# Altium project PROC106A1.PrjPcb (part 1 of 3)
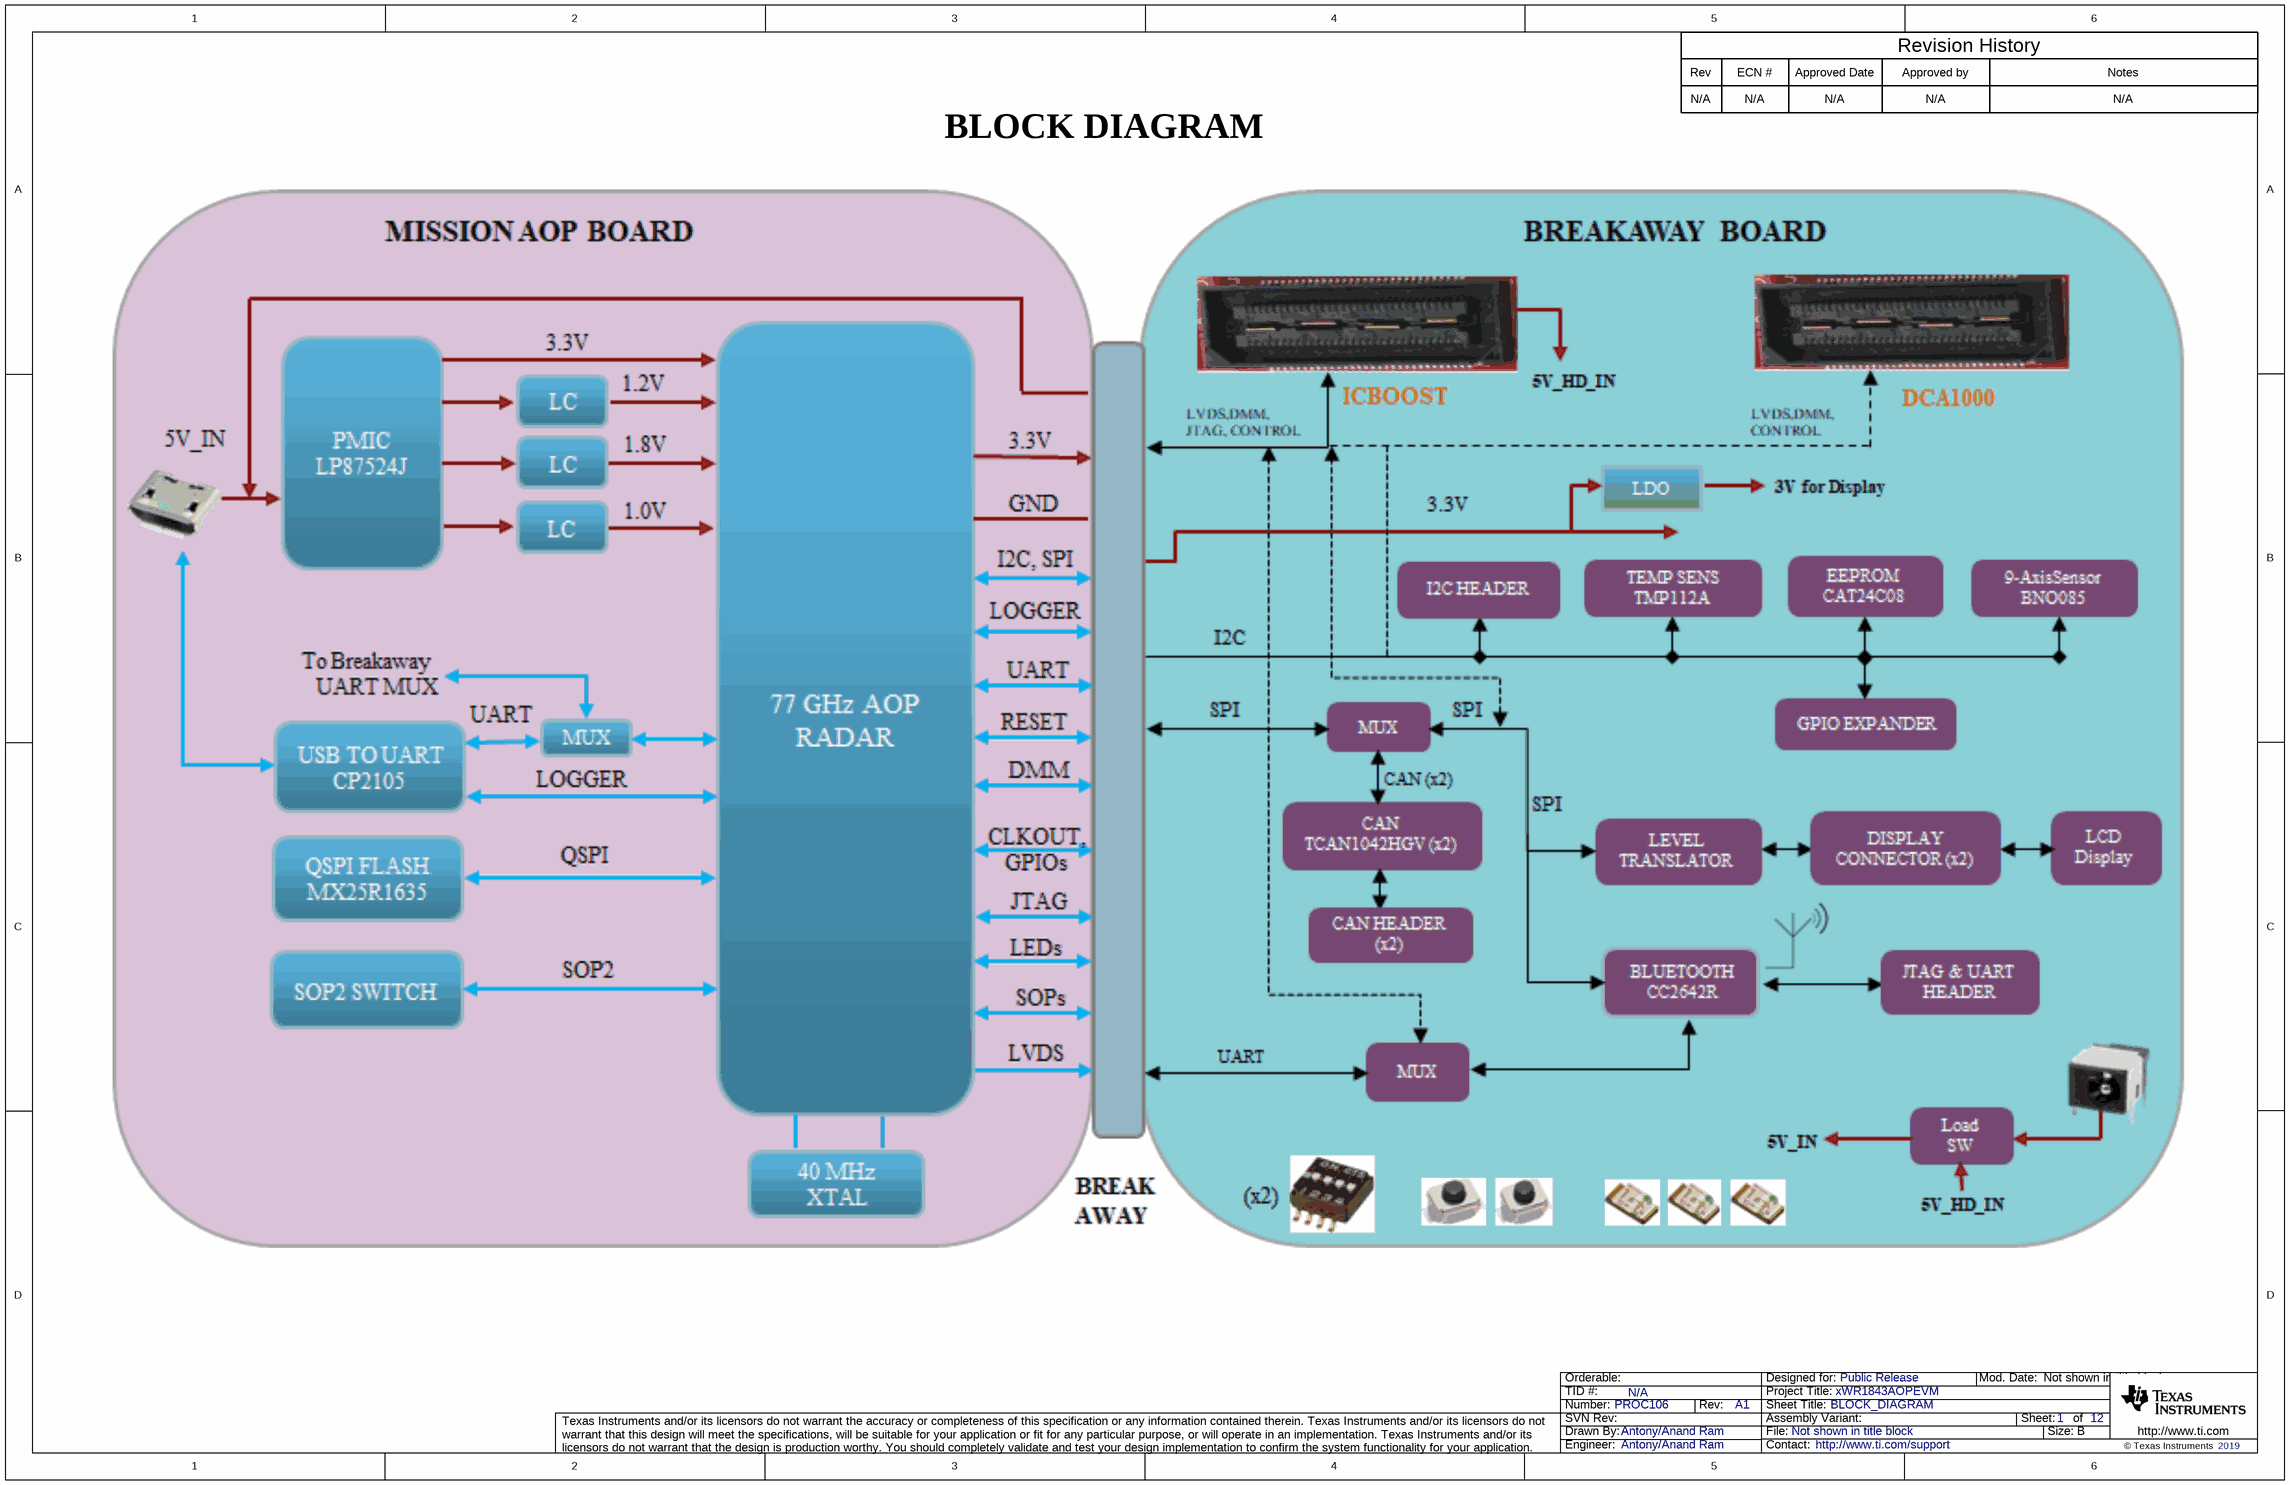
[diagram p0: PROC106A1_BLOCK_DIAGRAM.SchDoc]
CopyrightYear: 2019; PCB_Layout: Mistral Team; PCB_Rev: A1; PRJ_Customer: Public Release; PRJ_Engineer: Antony/Anand Ram; PRJ_Number: PROC106; PRJ_Title: xWR1843AOPEVM; SCH_Rev: A1; TechSupport: http://www.ti.com/support; TID: N/A
12 sheets, 430 parts. Net scope: flat (ports and power ports of the same name join across sheets).
Board file: PROC106A1.PcbDoc
Sheets:
  PROC106A1_BLOCK_DIAGRAM.SchDoc
  PROC106A1_TABLEOFCONTENTS.SchDoc
  PROC106A1_AOP_IO.SchDoc
  PROC106A1_AOP_PWR.SchDoc
  PROC106A1_PMIC.SchDoc
  PROC106A1_FLASH_USB_TO_UART.SchDoc
  PROC106A1_HD_CONN_PWR_SW.SchDoc
  PROC106A1_RST_GPIOs_I2C.SchDoc
  PROC106A1_BT_DISPLAY.SchDoc
  PROC106A1_ANALOG_MUX.SchDoc
  PROC106A1_CAN_INTERFACE.SchDoc
  PROC106A1_Hardware.schdoc

## Sheet PROC106A1_BLOCK_DIAGRAM.SchDoc: BLOCK_DIAGRAM
size 431 x 279 mm; Date: Not shown in title block; ApprovedBy: Not shown in title block; CheckedBy: Not shown in title block; Author: Not shown in title block; CompanyName: Not shown in title block; DrawnBy: Antony/Anand Ram; Engineer: Not shown in title block; Organization: Not shown in title block; Address1: Not shown in title block; Address2: Not shown in title block; Address3: Not shown in title block; Address4: Not shown in title block; DocumentNumber: 1; Revision: Use project parameter SCH_Rev; SheetNumber: 1; SheetTotal: 12; PageSetup: Record=PageOptions¦CenterHorizontal=True¦CenterVertical=True¦PrintScale=1.00¦XCorrection=1.00¦YCorrection=1.00¦PrintKind=0¦BorderSize=5000000¦LeftOffset=0¦BottomOffset=0¦Orientation=2¦PaperLength=1000¦PaperWidth=1000¦Scale=100¦PaperSource=15¦PrintQuality=600¦MediaType=1¦DitherType=10¦PaperKind=Letter¦PrintScaleMode=1

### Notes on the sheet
- Rev
- N/A
- ECN #
- Approved Date
- Approved by
- Revision History
- Notes
- BLOCK DIAGRAM

## Sheet PROC106A1_TABLEOFCONTENTS.SchDoc: TABLE_OF_CONTENTS
size 431 x 279 mm; Date: Not shown in title block; ApprovedBy: Not shown in title block; CheckedBy: Not shown in title block; Author: Not shown in title block; CompanyName: Not shown in title block; DrawnBy: Antony/Anand Ram; Engineer: Not shown in title block; Organization: Not shown in title block; Address1: Not shown in title block; Address2: Not shown in title block; Address3: Not shown in title block; Address4: Not shown in title block; DocumentNumber: 2; Revision: Use project parameter SCH_Rev; SheetNumber: 2; SheetTotal: 12; PageSetup: Record=PageOptions¦CenterHorizontal=True¦CenterVertical=True¦PrintScale=1.00¦XCorrection=1.00¦YCorrection=1.00¦PrintKind=0¦BorderSize=5000000¦LeftOffset=0¦BottomOffset=0¦Orientation=2¦PaperLength=1000¦PaperWidth=1000¦Scale=100¦PaperSource=15¦PrintQuality=600¦MediaType=1¦DitherType=10¦PaperKind=Letter¦PrintScaleMode=1
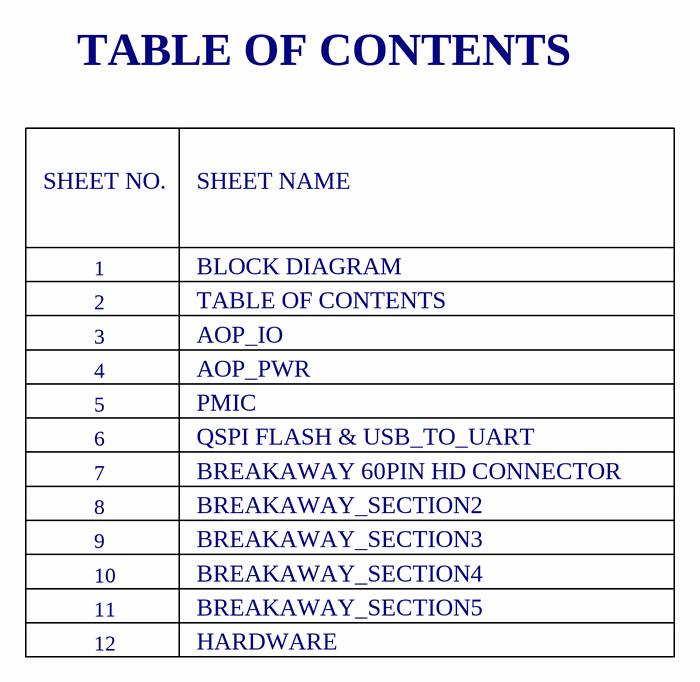
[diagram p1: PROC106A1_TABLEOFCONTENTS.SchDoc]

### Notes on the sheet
- TABLE OF CONTENTS
- SHEET NO.
- SHEET NAME
- 1
- 2
- 3
- BLOCK DIAGRAM
- AOP_IO
- 4
- 5
- AOP_PWR
- PMIC
- 7
- 8
- 6
- QSPI FLASH & USB_TO_UART
- BREAKAWAY 60PIN HD CONNECTOR
- BREAKAWAY_SECTION2
- 9
- 10
- BREAKAWAY_SECTION3
- BREAKAWAY_SECTION4
- 11
- 12
- HARDWARE
- BREAKAWAY_SECTION5

## Sheet PROC106A1_AOP_IO.SchDoc: AOP_IO
size 431 x 279 mm; Date: Not shown in title block; ApprovedBy: Not shown in title block; CheckedBy: Not shown in title block; Author: Not shown in title block; CompanyName: Not shown in title block; DrawnBy: Antony/Anand Ram; Engineer: Not shown in title block; Organization: Not shown in title block; Address1: Not shown in title block; Address2: Not shown in title block; Address3: Not shown in title block; Address4: Not shown in title block; DocumentNumber: 3; Revision: Use project parameter SCH_Rev; SheetNumber: 3; SheetTotal: 12; PageSetup: Record=PageOptions¦CenterHorizontal=True¦CenterVertical=True¦PrintScale=1.00¦XCorrection=1.00¦YCorrection=1.00¦PrintKind=0¦BorderSize=5000000¦LeftOffset=0¦BottomOffset=0¦Orientation=2¦PaperLength=1000¦PaperWidth=1000¦Scale=100¦PaperSource=15¦PrintQuality=600¦MediaType=1¦DitherType=10¦PaperKind=Letter¦PrintScaleMode=1
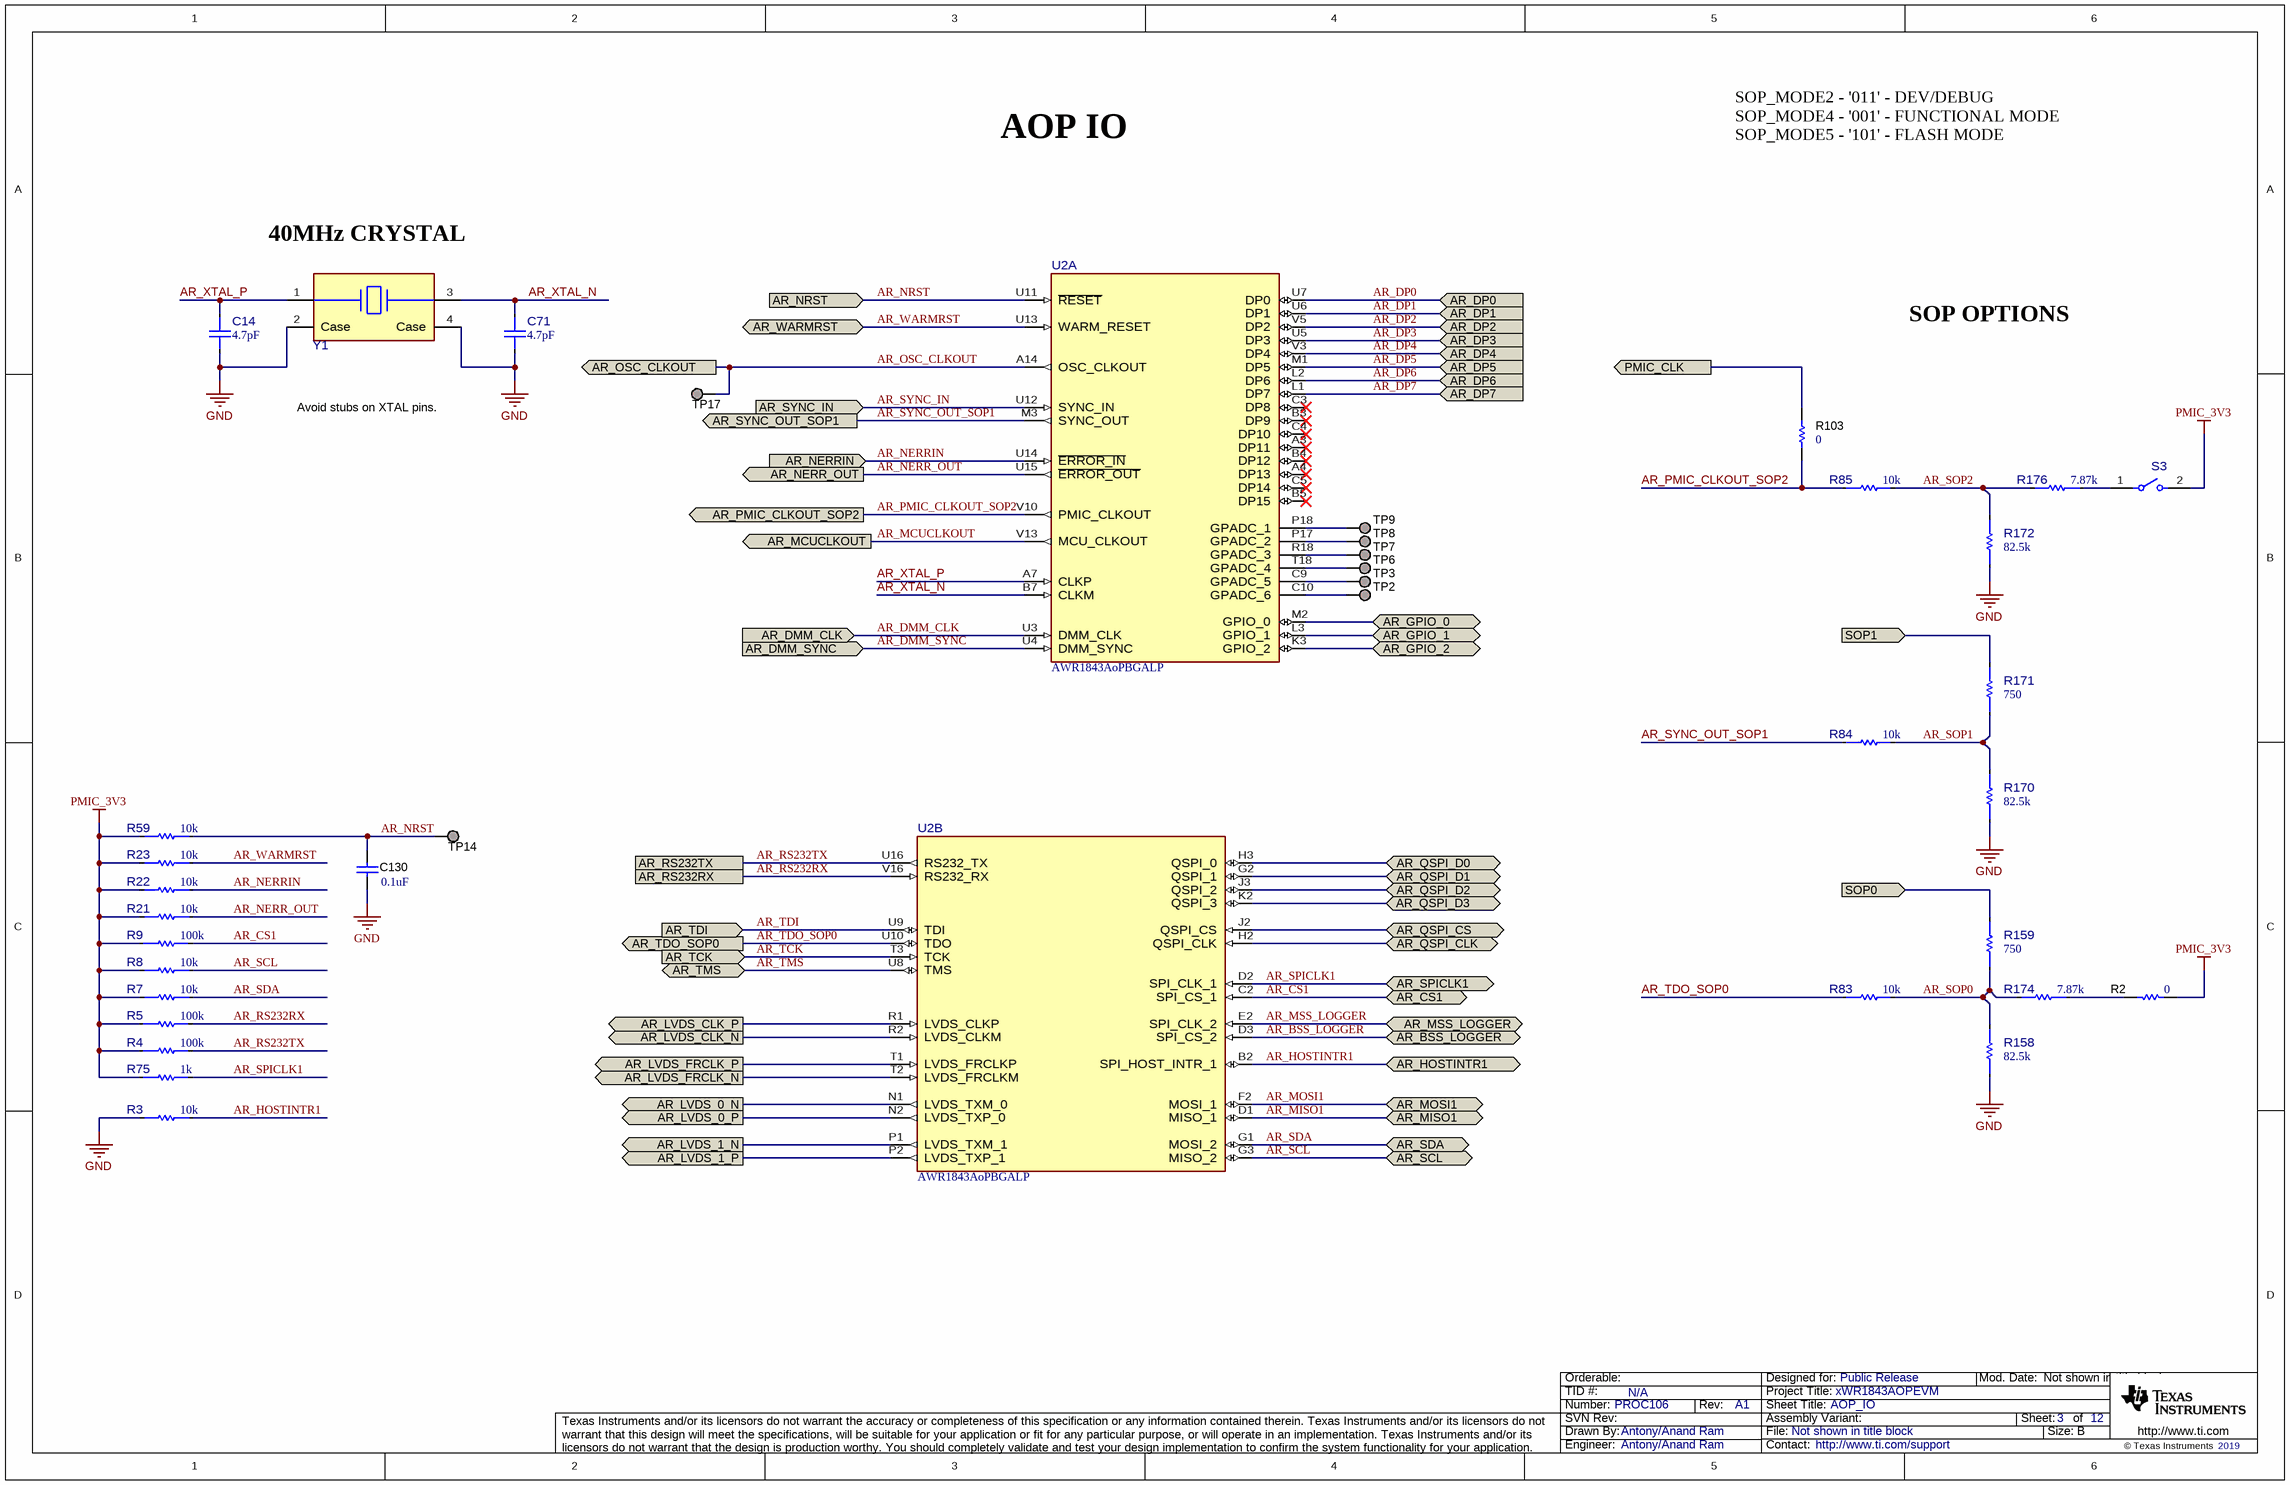
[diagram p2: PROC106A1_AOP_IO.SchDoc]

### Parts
C14  ValueDisplayed: 4.7pF  [FP-CGA1A2C0G1H4R7C030BA_0201-IPC_C]  (hidden comment: CGA1A2C0G1H4R7C030BA)
C71  ValueDisplayed: 4.7pF  [FP-CGA1A2C0G1H4R7C030BA_0201-IPC_C]  (hidden comment: CGA1A2C0G1H4R7C030BA)
C130  ValueDisplayed: 0.1uF  [0402L]  (hidden comment: GCM155R71C104KA55D)
R2  ValueDisplayed: 0  [0201L]  (hidden comment: ERJ-1GN0R00C)
R3  value 10k  [FP-ERA-1AEB103C_0201-IPC_C]  (hidden comment: ERA-1AEB103C)
R4  value 100k  [FP-ERJ-1GNF1003C_0201-IPC_C]  (hidden comment: ERJ-1GNF1003C)
R5  value 100k  [FP-ERJ-1GNF1003C_0201-IPC_C]  (hidden comment: ERJ-1GNF1003C)
R7  value 10k  [FP-ERA-1AEB103C_0201-IPC_C]  (hidden comment: ERA-1AEB103C)
R8  value 10k  [FP-ERA-1AEB103C_0201-IPC_C]  (hidden comment: ERA-1AEB103C)
R9  value 100k  [FP-ERJ-1GNF1003C_0201-IPC_C]  (hidden comment: ERJ-1GNF1003C)
R21  value 10k  [FP-ERA-1AEB103C_0201-IPC_C]  (hidden comment: ERA-1AEB103C)
R22  value 10k  [FP-ERA-1AEB103C_0201-IPC_C]  (hidden comment: ERA-1AEB103C)
R23  value 10k  [FP-ERA-1AEB103C_0201-IPC_C]  (hidden comment: ERA-1AEB103C)
R59  value 10k  [FP-ERA-1AEB103C_0201-IPC_C]  (hidden comment: ERA-1AEB103C)
R75  value 1k  [FP-ERJ-1GNJ102C_0201-IPC_C]  (hidden comment: ERJ-1GNJ102C)
R83  value 10k  [FP-ERA-1AEB103C_0201-IPC_C]  (hidden comment: ERA-1AEB103C)
R84  value 10k  [FP-ERA-1AEB103C_0201-IPC_C]  (hidden comment: ERA-1AEB103C)
R85  value 10k  [FP-ERA-1AEB103C_0201-IPC_C]  (hidden comment: ERA-1AEB103C)
R103  ValueDisplayed: 0  [0201L]  (hidden comment: ERJ-1GN0R00C)
R158  value 82.5k  [FP-ERJ-1GNF8252C_0201-IPC_C]  (hidden comment: ERJ-1GNF8252C)
R159  value 750  [FP-ERJ-1GNJ751C_0201-IPC_C]  (hidden comment: ERJ-1GNJ751C)
R170  value 82.5k  [FP-ERJ-1GNF8252C_0201-IPC_C]  (hidden comment: ERJ-1GNF8252C)
R171  value 750  [FP-ERJ-1GNJ751C_0201-IPC_C]  (hidden comment: ERJ-1GNJ751C)
R172  value 82.5k  [FP-ERJ-1GNF8252C_0201-IPC_C]  (hidden comment: ERJ-1GNF8252C)
R174  value 7.87k  [FP-ERJ-1GNF7871C_0201-IPC_C]  (hidden comment: ERJ-1GNF7871C)
R176  value 7.87k  [FP-ERJ-1GNF7871C_0201-IPC_C]  (hidden comment: ERJ-1GNF7871C)
S3  CHS-01TA  [FP-CHS-01TA_SMT_SW_5MM4_2MM5-MFG]  (value not drawn)
TP2  TESTPOINT  [TP_25MIL-SMT]  (value not drawn)  (no BOM)
TP3  TESTPOINT  [TP_25MIL-SMT]  (value not drawn)  (no BOM)
TP6  TESTPOINT  [TP_25MIL-SMT]  (value not drawn)  (no BOM)
TP7  TESTPOINT  [TP_25MIL-SMT]  (value not drawn)  (no BOM)
TP8  TESTPOINT  [TP_25MIL-SMT]  (value not drawn)  (no BOM)
TP9  TESTPOINT  [TP_25MIL-SMT]  (value not drawn)  (no BOM)
TP14  TESTPOINT  [TP_25MIL-SMT]  (value not drawn)  (no BOM)
TP17  TESTPOINT  [TP_25MIL-SMT]  (value not drawn)  (no BOM)
U2  AWR1843AoPBGALP  [ALP0180A-MFG]  (parts A,B of 5)
Y1  FW4000044Q  [FP-FW4000044Q_4-SMD-2.0x1.6mm-MFG]  (value not drawn)

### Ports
AR_BSS_LOGGER (bidir), AR_CS1 (bidir), AR_DMM_CLK (in), AR_DMM_SYNC (in), AR_DP0 (in), AR_DP1 (in), AR_DP2 (in), AR_DP3 (in), AR_DP4 (in), AR_DP5 (in), AR_DP6 (in), AR_DP7 (in), AR_GPIO_0 (bidir), AR_GPIO_1 (bidir), AR_GPIO_2 (bidir), AR_HOSTINTR1 (bidir), AR_LVDS_0_N (out), AR_LVDS_0_P (out), AR_LVDS_1_N (out), AR_LVDS_1_P (out), AR_LVDS_CLK_N (out), AR_LVDS_CLK_P (out), AR_LVDS_FRCLK_N (out), AR_LVDS_FRCLK_P (out), AR_MCUCLKOUT (out), AR_MISO1 (bidir), AR_MOSI1 (bidir), AR_MSS_LOGGER (bidir), AR_NERR_OUT (out), AR_NERRIN (in), AR_NRST (in), AR_OSC_CLKOUT (out), AR_PMIC_CLKOUT_SOP2 (out), AR_QSPI_CLK (bidir), AR_QSPI_CS (bidir), AR_QSPI_D0 (bidir), AR_QSPI_D1 (bidir), AR_QSPI_D2 (bidir), AR_QSPI_D3 (bidir), AR_RS232RX, AR_RS232TX, AR_SCL (bidir), AR_SDA (bidir), AR_SPICLK1 (bidir), AR_SYNC_IN (in), AR_SYNC_OUT_SOP1 (out), AR_TCK (in), AR_TDI (in), AR_TDO_SOP0 (out), AR_TMS (bidir), AR_WARMRST (bidir), PMIC_CLK (out), SOP0 (in), SOP1 (in)

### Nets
GND: C14.2 C71.2 C130.1 R3.2 R158.1 R170.1 R172.1 Y1.2(Case) Y1.4(Case)
PMIC_3V3: R2.2 R4.1 R5.1 R7.2 R8.2 R9.1 R21.2 R22.2 R23.2 R59.2 R75.1 S3.2
AR_BSS_LOGGER: U2.D3(SPI_CS_2) ; port AR_BSS_LOGGER
AR_CS1: R9.2 U2.C2(SPI_CS_1) ; port AR_CS1
AR_DMM_CLK: U2.U3(DMM_CLK) ; port AR_DMM_CLK
AR_DMM_SYNC: U2.U4(DMM_SYNC) ; port AR_DMM_SYNC
AR_DP0: U2.U7(DP0) ; port AR_DP0
AR_DP1: U2.U6(DP1) ; port AR_DP1
AR_DP2: U2.V5(DP2) ; port AR_DP2
AR_DP3: U2.U5(DP3) ; port AR_DP3
AR_DP4: U2.V3(DP4) ; port AR_DP4
AR_DP5: U2.M1(DP5) ; port AR_DP5
AR_DP6: U2.L2(DP6) ; port AR_DP6
AR_DP7: U2.L1(DP7) ; port AR_DP7
AR_GPIO_0: U2.M2(GPIO_0) ; port AR_GPIO_0
AR_GPIO_1: U2.L3(GPIO_1) ; port AR_GPIO_1
AR_GPIO_2: U2.K3(GPIO_2) ; port AR_GPIO_2
AR_HOSTINTR1: R3.1 U2.B2(SPI_HOST_INTR_1) ; port AR_HOSTINTR1
AR_LVDS_0_N: U2.N1(LVDS_TXM_0) ; port AR_LVDS_0_N
AR_LVDS_0_P: U2.N2(LVDS_TXP_0) ; port AR_LVDS_0_P
AR_LVDS_1_N: U2.P1(LVDS_TXM_1) ; port AR_LVDS_1_N
AR_LVDS_1_P: U2.P2(LVDS_TXP_1) ; port AR_LVDS_1_P
AR_LVDS_CLK_N: U2.R2(LVDS_CLKM) ; port AR_LVDS_CLK_N
AR_LVDS_CLK_P: U2.R1(LVDS_CLKP) ; port AR_LVDS_CLK_P
AR_LVDS_FRCLK_N: U2.T2(LVDS_FRCLKM) ; port AR_LVDS_FRCLK_N
AR_LVDS_FRCLK_P: U2.T1(LVDS_FRCLKP) ; port AR_LVDS_FRCLK_P
AR_MCUCLKOUT: U2.V13(MCU_CLKOUT) ; port AR_MCUCLKOUT
AR_MISO1: U2.D1(MISO_1) ; port AR_MISO1
AR_MOSI1: U2.F2(MOSI_1) ; port AR_MOSI1
AR_MSS_LOGGER: U2.E2(SPI_CLK_2) ; port AR_MSS_LOGGER
AR_NERR_OUT: R21.1 U2.U15(~{ERROR_OUT}) ; port AR_NERR_OUT
AR_NERRIN: R22.1 U2.U14(~{ERROR_IN}) ; port AR_NERRIN
AR_NRST: C130.2 R59.1 TP14.1 U2.U11(~{RESET}) ; port AR_NRST
AR_OSC_CLKOUT: TP17.1 U2.A14(OSC_CLKOUT) ; port AR_OSC_CLKOUT
AR_PMIC_CLKOUT_SOP2: R85.1 R103.1 U2.V10(PMIC_CLKOUT) ; port AR_PMIC_CLKOUT_SOP2
AR_QSPI_CLK: U2.H2(QSPI_CLK) ; port AR_QSPI_CLK
AR_QSPI_CS: U2.J2(QSPI_CS) ; port AR_QSPI_CS
AR_QSPI_D0: U2.H3(QSPI_0) ; port AR_QSPI_D0
AR_QSPI_D1: U2.G2(QSPI_1) ; port AR_QSPI_D1
AR_QSPI_D2: U2.J3(QSPI_2) ; port AR_QSPI_D2
AR_QSPI_D3: U2.K2(QSPI_3) ; port AR_QSPI_D3
AR_RS232RX: R5.2 U2.V16(RS232_RX) ; port AR_RS232RX
AR_RS232TX: R4.2 U2.U16(RS232_TX) ; port AR_RS232TX
AR_SCL: R8.1 U2.G3(MISO_2) ; port AR_SCL
AR_SDA: R7.1 U2.G1(MOSI_2) ; port AR_SDA
AR_SOP0: R83.2 R158.2 R159.1 R174.2
AR_SOP1: R84.2 R170.2 R171.1
AR_SOP2: R85.2 R172.2 R176.2
AR_SPICLK1: R75.2 U2.D2(SPI_CLK_1) ; port AR_SPICLK1
AR_SYNC_IN: U2.U12(SYNC_IN) ; port AR_SYNC_IN
AR_SYNC_OUT_SOP1: R84.1 U2.M3(SYNC_OUT) ; port AR_SYNC_OUT_SOP1
AR_TCK: U2.T3(TCK) ; port AR_TCK
AR_TDI: U2.U9(TDI) ; port AR_TDI
AR_TDO_SOP0: R83.1 U2.U10(TDO) ; port AR_TDO_SOP0
AR_TMS: U2.U8(TMS) ; port AR_TMS
AR_WARMRST: R23.1 U2.U13(WARM_RESET) ; port AR_WARMRST
AR_XTAL_N: C71.1 U2.B7(CLKM) Y1.3(2_Xtal)
AR_XTAL_P: C14.1 U2.A7(CLKP) Y1.1(1_Xtal)
PMIC_CLK: R103.2 ; port PMIC_CLK
SOP0: R159.2 ; port SOP0
SOP1: R171.2 ; port SOP1
NetR2_1: R2.1 R174.1
NetR176_1: R176.1 S3.1
NetTP2_1: TP2.1 U2.C10(GPADC_6)
NetTP3_1: TP3.1 U2.C9(GPADC_5)
NetTP6_1: TP6.1 U2.T18(GPADC_4)
NetTP7_1: TP7.1 U2.R18(GPADC_3)
NetTP8_1: TP8.1 U2.P17(GPADC_2)
NetTP9_1: TP9.1 U2.P18(GPADC_1)

Not connected (* = marked no-connect by the designer): U2 A3(DP11)* A4(DP13)* B3(DP9)* B4(DP12)* B5(DP15)* C3(DP8)* C4(DP10)* C5(DP14)*

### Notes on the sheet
- AOP IO
- SOP_MODE2 - '011' - DEV/DEBUG
  SOP_MODE4 - '001' - FUNCTIONAL MODE
  SOP_MODE5 - '101' - FLASH MODE
- 40MHz CRYSTAL
- SOP OPTIONS
- Avoid stubs on XTAL pins.

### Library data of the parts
C14 C71 = CMP-0090493-1: Cap Ceramic 4.7pF 50V C0G 0.25pF Pad SMD 0201 125°C Automotive T/R; Manufacturer: TDK; AEC Grade: Grade 1; AEC Qualified: Yes; SizeZ_mm: 0.4mm; TempCo: 30ppm/°C
C130 = CMP-0006351-2: CAP, CERM, 0.1 uF, 16 V, +/- 10%, X7R, 0402; Manufacturer: MuRata; Cap_F: 100nF; SizeZ_mm: 0.6; VDC_V: 16V; AEC Category: Q200; Cap_Case: 0402; Polarized: N; SizeArea_mm2: 0.5; SizeAreaWB_mm2: 3; SizeX_mm: 1; TaMax_C: 125°C; TaMin_C: -55°C; U/M: EA; Value1: Unknown; Value: 0.1uF
R2 R103 = CMP-0065361-1: RES, 0, 5%, .05 W, AEC-Q200 Grade 0, 0201; Manufacturer: Panasonic; AEC Qualified: Y; Power_W: 50mW; SizeZ_mm: 0.26; TempCo: ppm/C; AEC Category: Q200; EIA_Code: E24; Green_Lifecycle: Not Set; Green_REACh: Incomplete; SizeArea_mm2: 0.18; SizeX_mm: 0.6; SizeY_mm: 0.3; U/M: EA; Value2: .05W; Value: 0; Value_Code: 0000
R3 R7 R8 R21-R23 R59 R83-R85 = CMP-0090084-1: RES SMD 10K OHM 0.1% 1/20W 0201; Manufacturer: Panasonic; AEC Qualified: No; Power_W: 50mW; SizeZ_mm: 0.26mm; TempCo: 25ppm/°C; VDC_V: 25V
R4 R5 R9 = CMP-0090298-1: 100 kOhms ±1% 0.05W, 1/20W Chip Resistor 0201 (0603 Metric) Automotive AEC-Q200 Thick Film; Manufacturer: Panasonic Electronic Components; AEC Grade: Grade 1; AEC Qualified: Yes; Power_W: 50mW; SizeZ_mm: 0.26mm; TempCo: 200ppm/°C; VDC_V: 25V
R75 = CMP-0090500-1: 1 kOhms ±5% 0.05W, 1/20W Chip Resistor 0201 (0603 Metric) Automotive AEC-Q200 Thick Film; Manufacturer: Panasonic Electronic Components; AEC Grade: Grade 1; AEC Qualified: Yes; Power_W: 50mW; SizeZ_mm: 0.26mm; TempCo: 200ppm/°C; VDC_V: 25V
R158 R170 R172 = CMP-0090499-1: Res Thick Film 0201 82.5K Ohm 1% 1/20W ±200ppm/°C Molded SMD SMD T/R; Manufacturer: Panasonic; AEC Grade: Grade 1; AEC Qualified: Yes; Power_W: 50mW; SizeZ_mm: 0.26mm; VDC_V: 25V
R159 R171 = CMP-0090503-1: Res Thick Film 0201 750 Ohm 5% 0.05W(1/20W) ±200ppm/C Pad SMD Automotive T/R; Manufacturer: Panasonic Electronic Components; AEC Grade: Grade 1; AEC Qualified: Yes; Power_W: 50mW; SizeZ_mm: 0.26mm; TempCo: 200ppm/°C; VDC_V: 25V
R174 R176 = CMP-0090498-1: Res Thick Film 0201 7.87K Ohm 1% 1/20W ±200ppm/°C Molded SMD SMD T/R; Manufacturer: Panasonic; AEC Grade: Grade 1; AEC Qualified: Yes; Power_W: 50mW; SizeZ_mm: 0.26mm; VDC_V: 25V
S3 = CMP-0087181-1: SWITCH SLIDE DIP SPST 100MA 6V; Manufacturer: Nidec Copal Electronics; PositionCount: 1; SizeZ_mm: 2.5mm; Symbol Name: SYM-CHS-01TA
TP2 TP3 TP6-TP9 TP14 TP17 = CMP-0078143-3: TEST POINT.  No entry in BOM.
U2 = CMP-0090288-2: Manufacturer: Texas Instruments; Standoff Height: 0.31mm; SizeZ_mm: 0.965mm; AEC Category: Q200; CompType: IC
Y1 = CMP-0090505-1: 40MHz ±10ppm Crystal 8pF 50 Ohms 4-SMD, No Lead; Manufacturer: Diodes; AEC Qualified: Yes; Frequency Stability: 50ppm; SizeZ_mm: 0.55mm; AEC Grade: Grade 1; Esr: 50

## Sheet PROC106A1_AOP_PWR.SchDoc: AOP_POWER
size 431 x 279 mm; Date: Not shown in title block; ApprovedBy: Not shown in title block; CheckedBy: Not shown in title block; Author: Not shown in title block; CompanyName: Not shown in title block; DrawnBy: Antony/Anand Ram; Engineer: Not shown in title block; Organization: Not shown in title block; Address1: Not shown in title block; Address2: Not shown in title block; Address3: Not shown in title block; Address4: Not shown in title block; DocumentNumber: 4; Revision: Use project parameter SCH_Rev; SheetNumber: 4; SheetTotal: 12; PageSetup: Record=PageOptions¦CenterHorizontal=True¦CenterVertical=True¦PrintScale=1.00¦XCorrection=1.00¦YCorrection=1.00¦PrintKind=0¦BorderSize=5000000¦LeftOffset=0¦BottomOffset=0¦Orientation=2¦PaperLength=1000¦PaperWidth=1000¦Scale=100¦PaperSource=15¦PrintQuality=600¦MediaType=1¦DitherType=10¦PaperKind=Letter¦PrintScaleMode=1
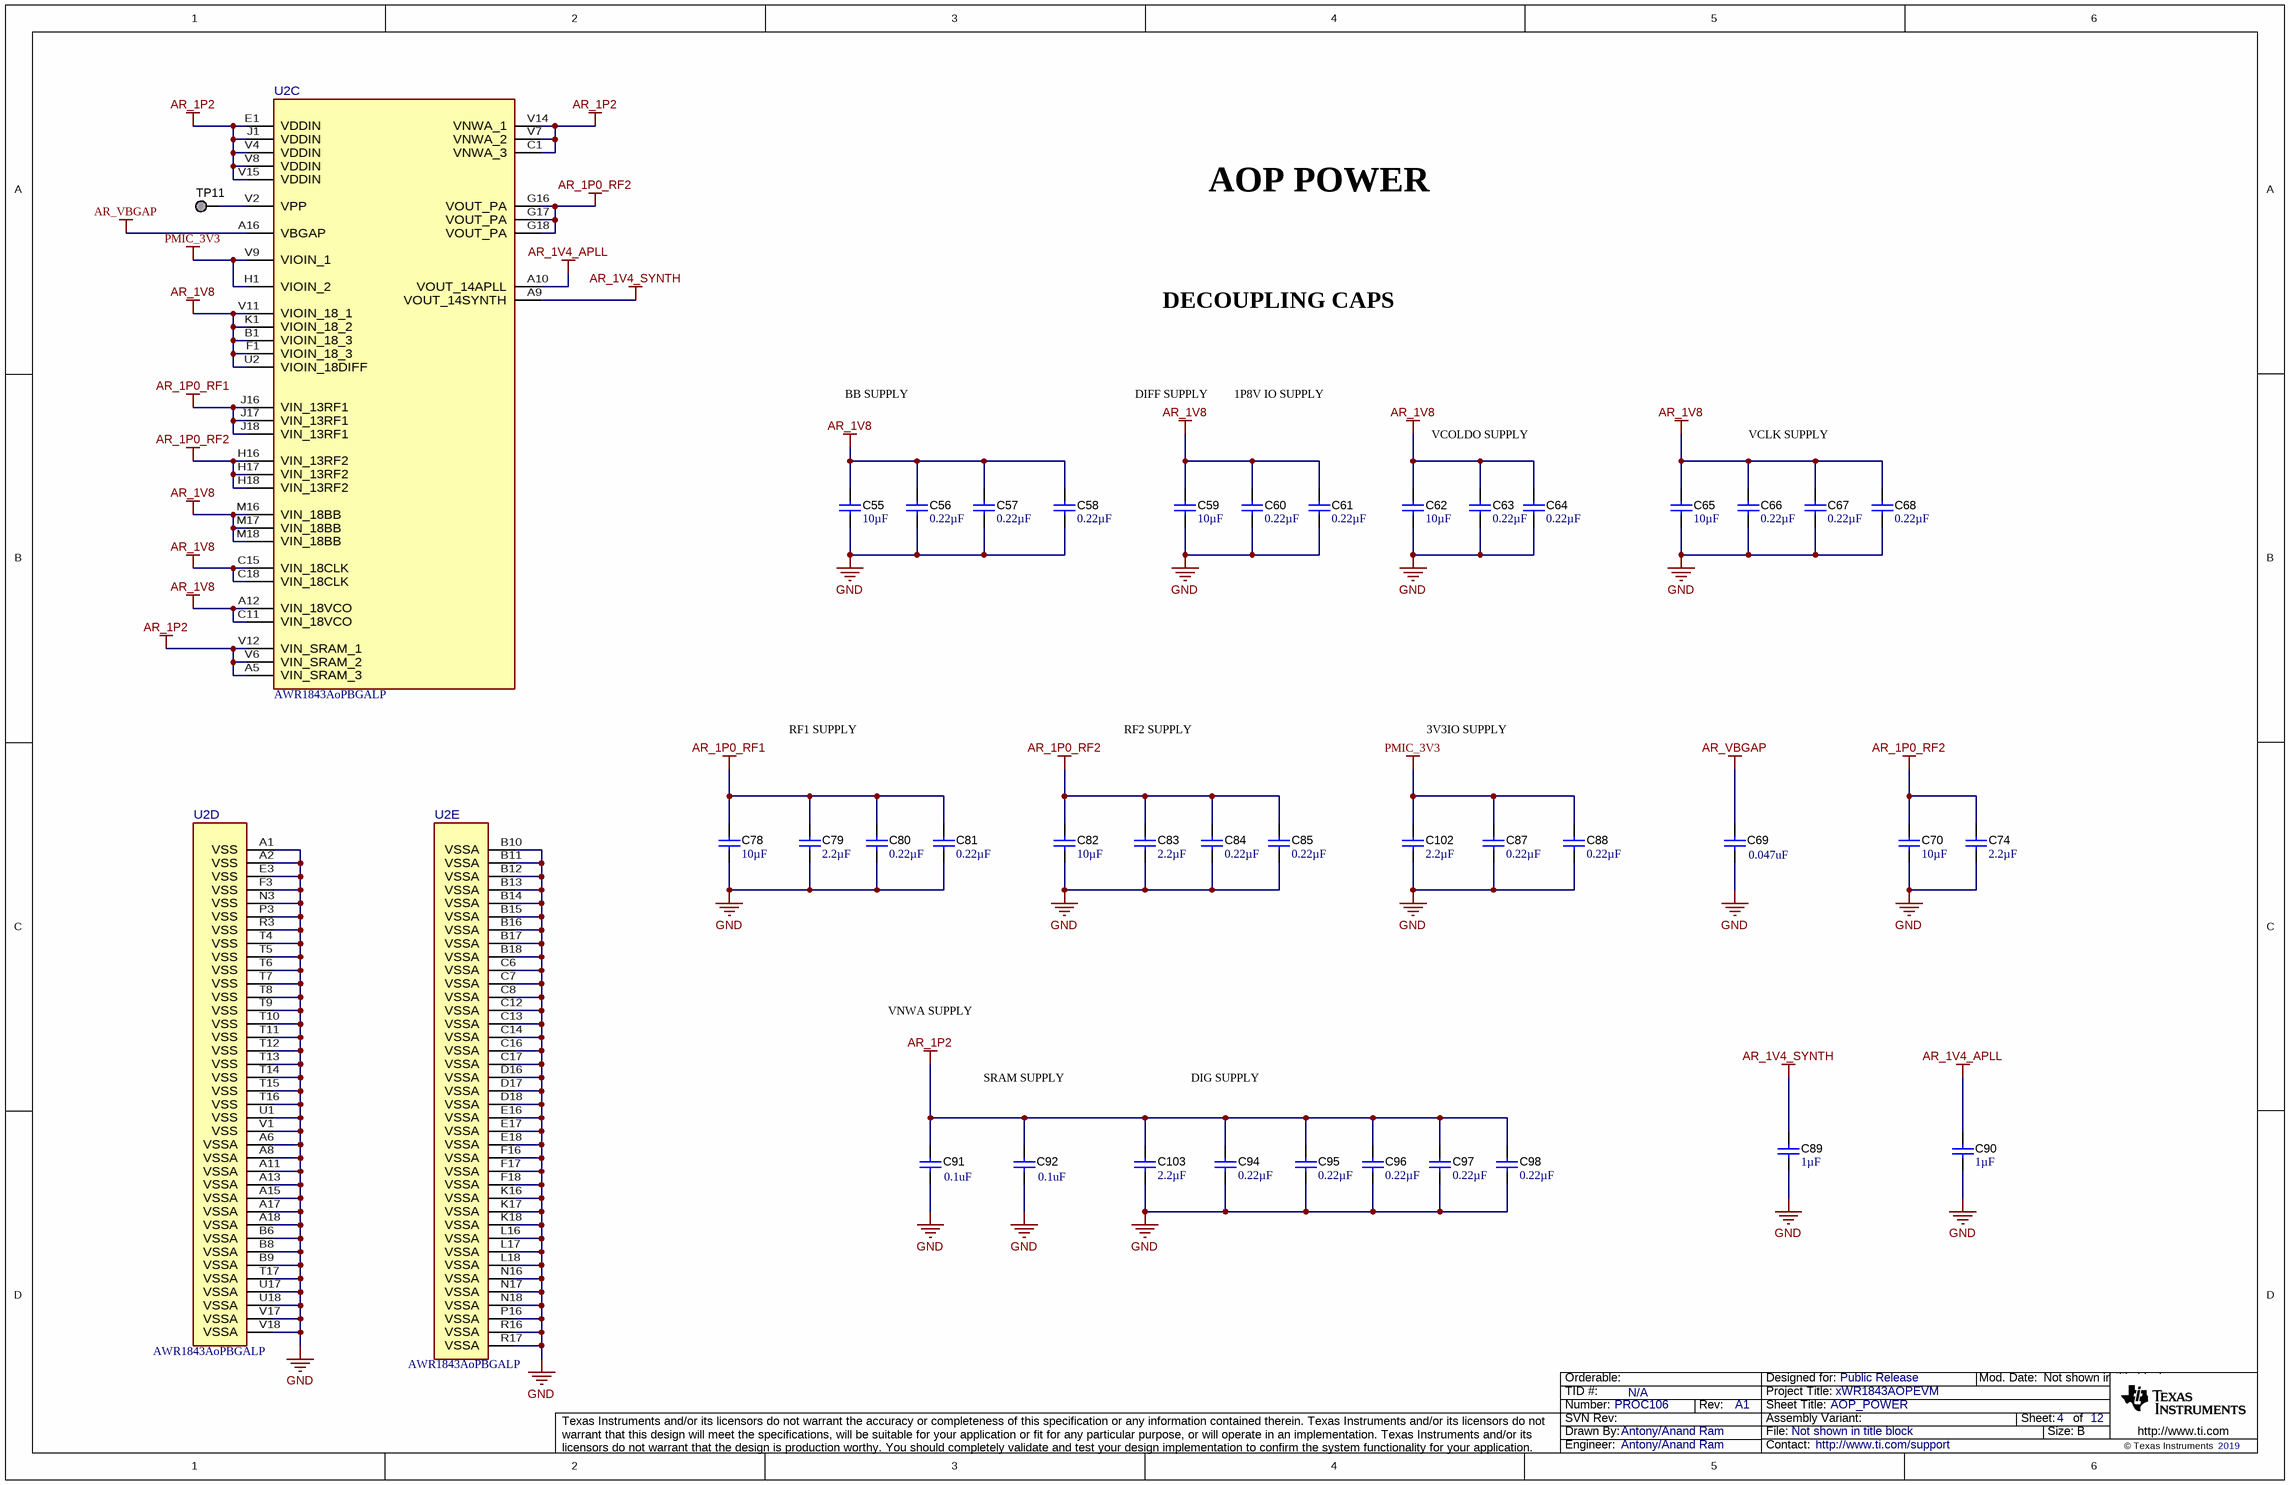
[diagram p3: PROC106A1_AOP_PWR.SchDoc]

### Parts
C55  Cap_F: 10µF  [0805L]  (hidden comment: GCM21BR71A106KE22L)
C56  ValueDisplayed: 0.22µF  [0402L]  (hidden comment: GCM155R71C224KE02D)
C57  ValueDisplayed: 0.22µF  [0402L]  (hidden comment: GCM155R71C224KE02D)
C58  ValueDisplayed: 0.22µF  [0402L]  (hidden comment: GCM155R71C224KE02D)
C59  Cap_F: 10µF  [0805L]  (hidden comment: GCM21BR71A106KE22L)
C60  ValueDisplayed: 0.22µF  [0402L]  (hidden comment: GCM155R71C224KE02D)
C61  ValueDisplayed: 0.22µF  [0402L]  (hidden comment: GCM155R71C224KE02D)
C62  Cap_F: 10µF  [0805L]  (hidden comment: GCM21BR71A106KE22L)
C63  ValueDisplayed: 0.22µF  [0402L]  (hidden comment: GCM155R71C224KE02D)
C64  ValueDisplayed: 0.22µF  [0402L]  (hidden comment: GCM155R71C224KE02D)
C65  Cap_F: 10µF  [0805L]  (hidden comment: GCM21BR71A106KE22L)
C66  ValueDisplayed: 0.22µF  [0402L]  (hidden comment: GCM155R71C224KE02D)
C67  ValueDisplayed: 0.22µF  [0402L]  (hidden comment: GCM155R71C224KE02D)
C68  ValueDisplayed: 0.22µF  [0402L]  (hidden comment: GCM155R71C224KE02D)
C69  ValueDisplayed: 0.047uF  [0402L]  (hidden comment: CGA2B3X7R1H473K050BB)
C70  Cap_F: 10µF  [0805L]  (hidden comment: GCM21BR71A106KE22L)
C74  Cap_F: 2.2µF  [0603L]  (hidden comment: GCM188R70J225KE22D)
C78  Cap_F: 10µF  [0805L]  (hidden comment: GCM21BR71A106KE22L)
C79  Cap_F: 2.2µF  [0603L]  (hidden comment: GCM188R70J225KE22D)
C80  ValueDisplayed: 0.22µF  [0402L]  (hidden comment: GCM155R71C224KE02D)
C81  ValueDisplayed: 0.22µF  [0402L]  (hidden comment: GCM155R71C224KE02D)
C82  Cap_F: 10µF  [0805L]  (hidden comment: GCM21BR71A106KE22L)
C83  Cap_F: 2.2µF  [0603L]  (hidden comment: GCM188R70J225KE22D)
C84  ValueDisplayed: 0.22µF  [0402L]  (hidden comment: GCM155R71C224KE02D)
C85  ValueDisplayed: 0.22µF  [0402L]  (hidden comment: GCM155R71C224KE02D)
C87  ValueDisplayed: 0.22µF  [0402L]  (hidden comment: GCM155R71C224KE02D)
C88  ValueDisplayed: 0.22µF  [0402L]  (hidden comment: GCM155R71C224KE02D)
C89  Cap_F: 1µF  [0603L]  (hidden comment: GCM188R71C105KA64D)
C90  Cap_F: 1µF  [0603L]  (hidden comment: GCM188R71C105KA64D)
C91  ValueDisplayed: 0.1uF  [0402L]  (hidden comment: GCM155R71C104KA55D)
C92  ValueDisplayed: 0.1uF  [0402L]  (hidden comment: GCM155R71C104KA55D)
C94  ValueDisplayed: 0.22µF  [0402L]  (hidden comment: GCM155R71C224KE02D)
C95  ValueDisplayed: 0.22µF  [0402L]  (hidden comment: GCM155R71C224KE02D)
C96  ValueDisplayed: 0.22µF  [0402L]  (hidden comment: GCM155R71C224KE02D)
C97  ValueDisplayed: 0.22µF  [0402L]  (hidden comment: GCM155R71C224KE02D)
C98  ValueDisplayed: 0.22µF  [0402L]  (hidden comment: GCM155R71C224KE02D)
C102  Cap_F: 2.2µF  [0603L]  (hidden comment: GCM188R70J225KE22D)
C103  Cap_F: 2.2µF  [0603L]  (hidden comment: GCM188R70J225KE22D)
TP11  TP_SM_1MM  [TP_SM_1MM]  (value not drawn)  (no BOM)
U2  AWR1843AoPBGALP  [ALP0180A-MFG]  (parts C,D,E of 5)

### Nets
AR_1P0_RF1: C78.1 C79.1 C80.1 C81.1 U2.J16(VIN_13RF1) U2.J17(VIN_13RF1) U2.J18(VIN_13RF1)
AR_1P0_RF2: C70.1 C74.1 C82.1 C83.1 C84.1 C85.1 U2.G16(VOUT_PA) U2.G17(VOUT_PA) U2.G18(VOUT_PA) U2.H16(VIN_13RF2) U2.H17(VIN_13RF2) U2.H18(VIN_13RF2)
AR_1P2: C91.2 C92.2 C94.1 C95.1 C96.1 C97.1 C98.1 C103.1 U2.A5(VIN_SRAM_3) U2.C1(VNWA_3) U2.E1(VDDIN) U2.J1(VDDIN) U2.V4(VDDIN) U2.V6(VIN_SRAM_2) U2.V7(VNWA_2) U2.V8(VDDIN) U2.V12(VIN_SRAM_1) U2.V14(VNWA_1) U2.V15(VDDIN)
AR_1V4_APLL: C90.1 U2.A10(VOUT_14APLL)
AR_1V4_SYNTH: C89.1 U2.A9(VOUT_14SYNTH)
AR_1V8: C55.1 C56.1 C57.1 C58.1 C59.1 C60.1 C61.1 C62.1 C63.1 C64.1 C65.1 C66.1 C67.1 C68.1 U2.A12(VIN_18VCO) U2.B1(VIOIN_18_3) U2.C11(VIN_18VCO) U2.C15(VIN_18CLK) U2.C18(VIN_18CLK) U2.F1(VIOIN_18_3) U2.K1(VIOIN_18_2) U2.M16(VIN_18BB) U2.M17(VIN_18BB) U2.M18(VIN_18BB) U2.U2(VIOIN_18DIFF) U2.V11(VIOIN_18_1)
AR_VBGAP: C69.1 U2.A16(VBGAP)
GND: C55.2 C56.2 C57.2 C58.2 C59.2 C60.2 C61.2 C62.2 C63.2 C64.2 C65.2 C66.2 C67.2 C68.2 C69.2 C70.2 C74.2 C78.2 C79.2 C80.2 C81.2 C82.2 C83.2 C84.2 C85.2 C87.2 C88.2 C89.2 C90.2 C91.1 C92.1 C94.2 C95.2 C96.2 C97.2 C98.2 C102.2 C103.2 U2.A1(VSS) U2.A2(VSS) U2.A6(VSSA) U2.A8(VSSA) U2.A11(VSSA) U2.A13(VSSA) U2.A15(VSSA) U2.A17(VSSA) U2.A18(VSSA) U2.B6(VSSA) U2.B8(VSSA) U2.B9(VSSA) U2.B10(VSSA) U2.B11(VSSA) U2.B12(VSSA) U2.B13(VSSA) U2.B14(VSSA) U2.B15(VSSA) U2.B16(VSSA) U2.B17(VSSA) U2.B18(VSSA) U2.C6(VSSA) U2.C7(VSSA) U2.C8(VSSA) U2.C12(VSSA) U2.C13(VSSA) U2.C14(VSSA) U2.C16(VSSA) U2.C17(VSSA) U2.D16(VSSA) U2.D17(VSSA) U2.D18(VSSA) U2.E3(VSS) U2.E16(VSSA) U2.E17(VSSA) U2.E18(VSSA) U2.F3(VSS) U2.F16(VSSA) U2.F17(VSSA) U2.F18(VSSA) U2.K16(VSSA) U2.K17(VSSA) U2.K18(VSSA) U2.L16(VSSA) U2.L17(VSSA) U2.L18(VSSA) U2.N3(VSS) U2.N16(VSSA) U2.N17(VSSA) U2.N18(VSSA) U2.P3(VSS) U2.P16(VSSA) U2.R3(VSS) U2.R16(VSSA) U2.R17(VSSA) U2.T4(VSS) U2.T5(VSS) U2.T6(VSS) U2.T7(VSS) U2.T8(VSS) U2.T9(VSS) U2.T10(VSS) U2.T11(VSS) U2.T12(VSS) U2.T13(VSS) U2.T14(VSS) U2.T15(VSS) U2.T16(VSS) U2.T17(VSSA) U2.U1(VSS) U2.U17(VSSA) U2.U18(VSSA) U2.V1(VSS) U2.V17(VSSA) U2.V18(VSSA)
PMIC_3V3: C87.1 C88.1 C102.1 U2.H1(VIOIN_2) U2.V9(VIOIN_1)
NetTP11_1: TP11.1 U2.V2(VPP)

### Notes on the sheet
- AOP POWER
- DECOUPLING CAPS
- BB SUPPLY
- DIFF SUPPLY
- 1P8V IO SUPPLY
- VCOLDO SUPPLY
- VCLK SUPPLY
- RF1 SUPPLY
- RF2 SUPPLY
- 3V3IO SUPPLY
- VNWA SUPPLY
- SRAM SUPPLY
- DIG SUPPLY

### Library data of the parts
C55 C59 C62 C65 C70 C78 C82 = CMP-0008017-2: CAP, CERM, 10 uF, 10 V, +/- 10%, X7R, 0805; Manufacturer: MuRata; Value: 10uF; AEC Category: Q200; Cap_Case: 0805; Polarized: N; SizeArea_mm2: 2.5; SizeAreaWB_mm2: 6.75; SizeX_mm: 2; SizeY_mm: 1.25; SizeZ_mm: 1.45; TaMax_C: 125°C; TaMin_C: -55°C; U/M: EA; Value1: Unknown; Value2: 10V
C56-C58 C60 C61 C63 C64 C66-C68 C80 C81 C84 C85 C87 C88 C94-C98 = CMP-0078265-1: CAP, CERM, 0.22 µF, 16 V,+/- 10%, X7R, AEC-Q200 Grade 1, 0402; Manufacturer: MuRata; Value: 0.22uF; AEC Category: Q200; AEC Grade: 1; AEC Qualified: Y; Cap_Case: 0402; Cap_F: 220nF; Polarized: N; SizeArea_mm2: 0.5; SizeAreaWB_mm2: 3; SizeZ_mm: 0.6; TaMax_C: 125°C; TaMin_C: -55°C; U/M: EA; Value2: 16V
C69 = CMP-0006330-2: CAP, CERM, 0.047 uF, 50 V, +/- 10%, X7R, AEC-Q200 Grade 1, 0402; Manufacturer: TDK; SizeZ_mm: 0.6; AEC Qualified: Y; Cap_F: 47nF; VDC_V: 50V; AEC Grade: 1; AEC Category: Q200; Cap_Case: 0402; ESR_ohm: 0.06407; IRMS_A: 6.46122dA; Polarized: N; SizeArea_mm2: 0.5; SizeAreaWB_mm2: 3; TaMax_C: 125°C; TaMin_C: -55°C; U/M: EA; Value1: 0.06407 ohm
C74 C79 C83 C102 C103 = CMP-0007134-5: CAP, CERM, 2.2 uF, 6.3 V, +/- 10%, X7R, AEC-Q200 Grade 1, 0603; Manufacturer: MuRata; Value: 2.2uF; AEC Category: Q200; AEC Grade: 1; AEC Qualified: Y; Cap_Case: 0603; Polarized: N; SizeArea_mm2: 1.28; SizeAreaWB_mm2: 4.68; SizeX_mm: 1.6; SizeY_mm: 0.8; TaMax_C: 125°C; TaMin_C: -55°C; U/M: EA; Value1: Unknown; Value2: 6.3V
C89 C90 = CMP-0007136-5: CAP, CERM, 1 uF, 16 V, +/- 10%, X7R, AEC-Q200 Grade 1, 0603; Manufacturer: MuRata; TaMin_C: -55°C; Polarized: N; SizeAreaWB_mm2: 4.68; U/M: EA; Value: 1uF; TaMax_C: 125°C; SizeZ_mm: 1; SizeX_mm: 1.6; SizeY_mm: 0.8; Cap_Case: 0603; Value2: 16V; SizeArea_mm2: 1.28; AEC Qualified: Y; AEC Category: Q200; Value1: Unknown
C91 C92 = CMP-0006351-2: as C130 on sheet PROC106A1_AOP_IO
TP11 = CMP-0003825-1: 1mm Test Point, SMT; Manufacturer: Any
U2 = CMP-0090288-2: as U2 on sheet PROC106A1_AOP_IO

## Sheet PROC106A1_PMIC.SchDoc: PMIC
size 431 x 279 mm; Date: Not shown in title block; ApprovedBy: Not shown in title block; CheckedBy: Not shown in title block; Author: Not shown in title block; CompanyName: Not shown in title block; DrawnBy: Antony/Anand Ram; Engineer: Not shown in title block; Organization: Not shown in title block; Address1: Not shown in title block; Address2: Not shown in title block; Address3: Not shown in title block; Address4: Not shown in title block; DocumentNumber: 5; Revision: Use project parameter SCH_Rev; SheetNumber: 5; SheetTotal: 12; PageSetup: Record=PageOptions¦CenterHorizontal=True¦CenterVertical=True¦PrintScale=1.00¦XCorrection=1.00¦YCorrection=1.00¦PrintKind=0¦BorderSize=5000000¦LeftOffset=0¦BottomOffset=0¦Orientation=2¦PaperLength=1000¦PaperWidth=1000¦Scale=100¦PaperSource=15¦PrintQuality=600¦MediaType=1¦DitherType=10¦PaperKind=Letter¦PrintScaleMode=1
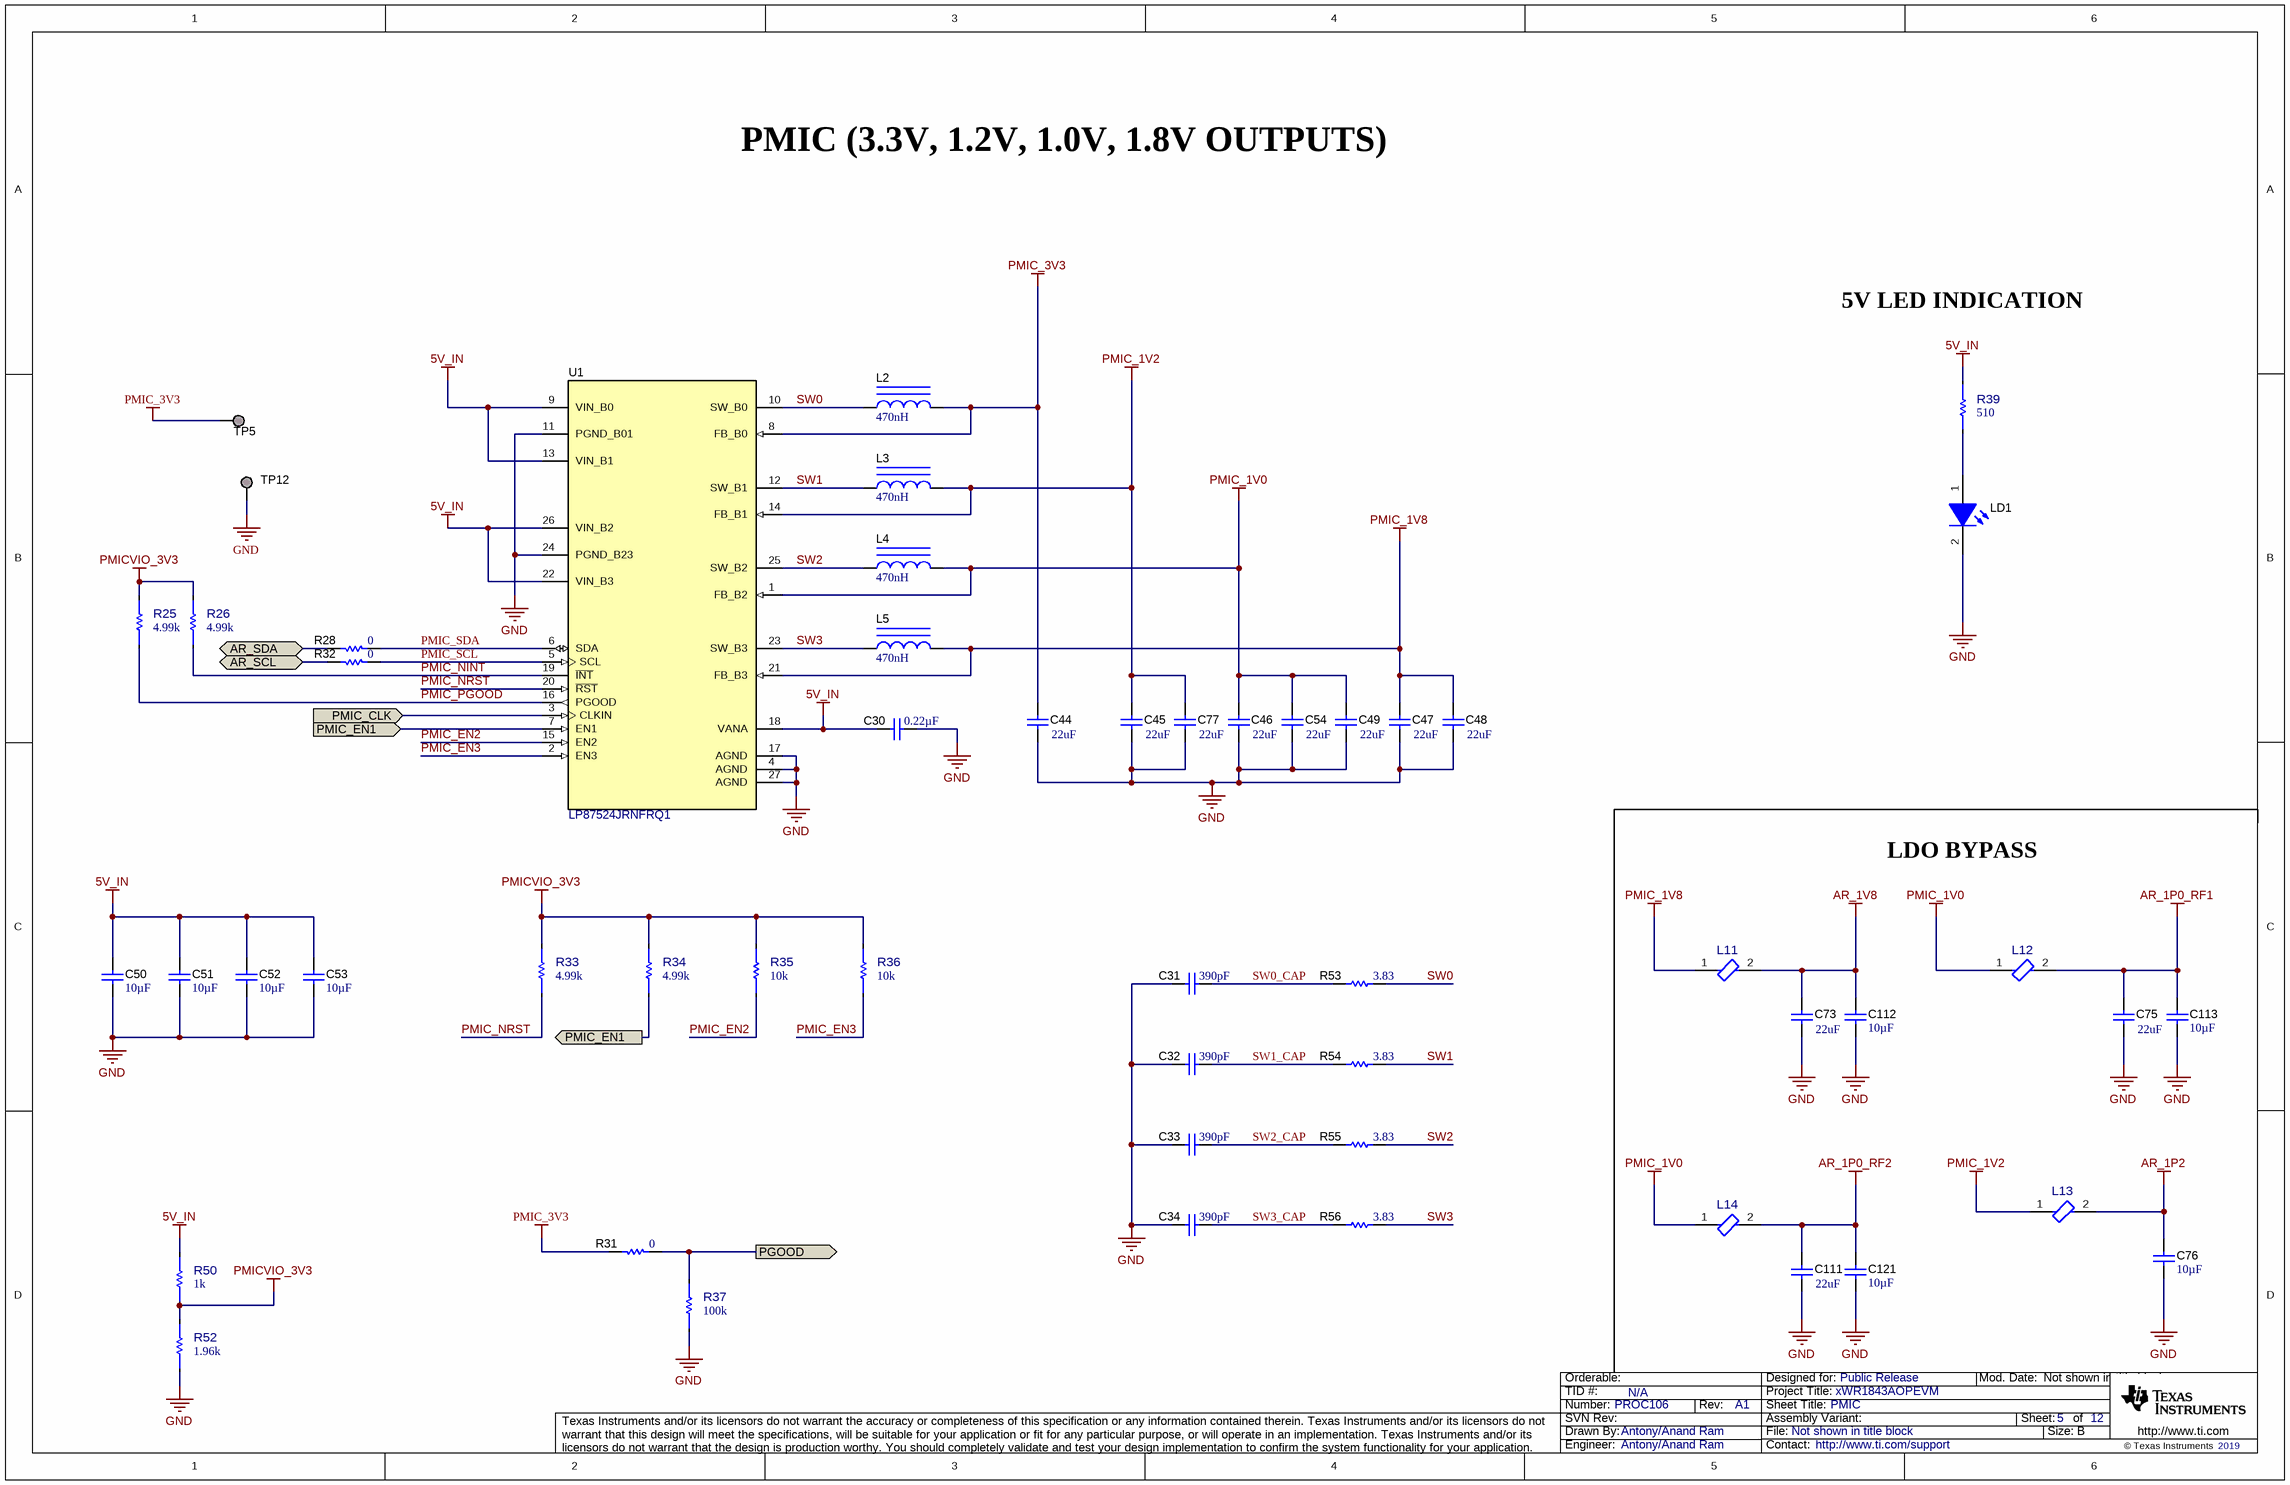
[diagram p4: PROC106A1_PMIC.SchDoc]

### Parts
C30  ValueDisplayed: 0.22µF  [0402L]  (hidden comment: GCM155R71C224KE02D)
C31  ValueDisplayed: 390pF  [0402L]  (hidden comment: CGA2B2C0G1H391J050BA)
C32  ValueDisplayed: 390pF  [0402L]  (hidden comment: CGA2B2C0G1H391J050BA)
C33  ValueDisplayed: 390pF  [0402L]  (hidden comment: CGA2B2C0G1H391J050BA)
C34  ValueDisplayed: 390pF  [0402L]  (hidden comment: CGA2B2C0G1H391J050BA)
C44  ValueDisplayed: 22uF  [1206_180L]  (hidden comment: GCM31CR71A226KE02L)
C45  ValueDisplayed: 22uF  [1206_180L]  (hidden comment: GCM31CR71A226KE02L)
C46  ValueDisplayed: 22uF  [1206_180L]  (hidden comment: GCM31CR71A226KE02L)
C47  ValueDisplayed: 22uF  [1206_180L]  (hidden comment: GCM31CR71A226KE02L)
C48  ValueDisplayed: 22uF  [1206_180L]  (hidden comment: GCM31CR71A226KE02L)
C49  ValueDisplayed: 22uF  [1206_180L]  (hidden comment: GCM31CR71A226KE02L)
C50  Cap_F: 10µF  [0805_HV1]  (hidden comment: GCM21BR71A106KE22L)
C51  Cap_F: 10µF  [0805_HV1]  (hidden comment: GCM21BR71A106KE22L)
C52  Cap_F: 10µF  [0805_HV1]  (hidden comment: GCM21BR71A106KE22L)
C53  Cap_F: 10µF  [0805_HV1]  (hidden comment: GCM21BR71A106KE22L)
C54  ValueDisplayed: 22uF  [1206_180L]  (hidden comment: GCM31CR71A226KE02L)
C73  ValueDisplayed: 22uF  [1206_180L]  (hidden comment: GCM31CR71A226KE02L)
C75  ValueDisplayed: 22uF  [1206_180L]  (hidden comment: GCM31CR71A226KE02L)
C76  Cap_F: 10µF  [0805L]  (hidden comment: GCM21BR71A106KE22L)
C77  ValueDisplayed: 22uF  [1206_180L]  (hidden comment: GCM31CR71A226KE02L)
C111  ValueDisplayed: 22uF  [1206_180L]  (hidden comment: GCM31CR71A226KE02L)
C112  Cap_F: 10µF  [0805L]  (hidden comment: GCM21BR71A106KE22L)
C113  Cap_F: 10µF  [0805L]  (hidden comment: GCM21BR71A106KE22L)
C121  Cap_F: 10µF  [0805L]  (hidden comment: GCM21BR71A106KE22L)
L2  ValueDisplayed: 470nH  [DFE252012P]  (hidden comment: DFE252012PD-R47M)
L3  ValueDisplayed: 470nH  [DFE252012P]  (hidden comment: DFE252012PD-R47M)
L4  ValueDisplayed: 470nH  [DFE252012P]  (hidden comment: DFE252012PD-R47M)
L5  ValueDisplayed: 470nH  [DFE252012P]  (hidden comment: DFE252012PD-R47M)
L11  MPZ2012S101ATD25  [FP-MPZ2012S101ATD25_0805-MFG]  (value not drawn)
L12  MPZ2012S101ATD25  [FP-MPZ2012S101ATD25_0805-MFG]  (value not drawn)
L13  MPZ2012S101ATD25  [FP-MPZ2012S101ATD25_0805-MFG]  (value not drawn)
L14  MPZ2012S101ATD25  [FP-MPZ2012S101ATD25_0805-MFG]  (value not drawn)
LD1  APHHS1005CGCK  [APHHS1005_Green]  (value not drawn)
R25  value 4.99k  [FP-ERJ-1GNF4991C_0201-IPC_C]  (hidden comment: ERJ-1GNF4991C)
R26  value 4.99k  [FP-ERJ-1GNF4991C_0201-IPC_C]  (hidden comment: ERJ-1GNF4991C)
R28  ValueDisplayed: 0  [0201L]  (hidden comment: ERJ-1GN0R00C)
R31  ValueDisplayed: 0  [0201L]  (hidden comment: ERJ-1GN0R00C)
R32  ValueDisplayed: 0  [0201L]  (hidden comment: ERJ-1GN0R00C)
R33  value 4.99k  [FP-ERJ-1GNF4991C_0201-IPC_C]  (hidden comment: ERJ-1GNF4991C)
R34  value 4.99k  [FP-ERJ-1GNF4991C_0201-IPC_C]  (hidden comment: ERJ-1GNF4991C)
R35  value 10k  [FP-ERA-1AEB103C_0201-IPC_C]  (hidden comment: ERA-1AEB103C)
R36  value 10k  [FP-ERA-1AEB103C_0201-IPC_C]  (hidden comment: ERA-1AEB103C)
R37  value 100k  [FP-ERJ-1GNF1003C_0201-IPC_C]  (hidden comment: ERJ-1GNF1003C)
R39  value 510  [FP-ERJ-1GNJ511C_0201-IPC_C]  (hidden comment: ERJ-1GNJ511C)
R50  value 1k  [FP-ERJ-1GNJ102C_0201-IPC_C]  (hidden comment: ERJ-1GNJ102C)
R52  value 1.96k  [FP-ERJ-1GNF1961C_0201-IPC_C]  (hidden comment: ERJ-1GNF1961C)
R53  ValueDisplayed: 3.83  [0402L]  (hidden comment: CRCW04023R83FKED)
R54  ValueDisplayed: 3.83  [0402L]  (hidden comment: CRCW04023R83FKED)
R55  ValueDisplayed: 3.83  [0402L]  (hidden comment: CRCW04023R83FKED)
R56  ValueDisplayed: 3.83  [0402L]  (hidden comment: CRCW04023R83FKED)
TP5  TESTPOINT  [TP_25MIL-SMT]  (value not drawn)  (no BOM)
TP12  TESTPOINT  [TP_VIA_060RND040]  (value not drawn)  (no BOM)
U1  LP87524JRNFRQ1  [RNF0026C]

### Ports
AR_SCL (bidir), AR_SDA (bidir), PGOOD (out), PMIC_CLK (in), PMIC_EN1 (in), PMIC_EN1 (out)

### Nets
5V_IN: C30.1 C50.1 C51.1 C52.1 C53.1 R39.1 R50.2 U1.9(VIN_B0) U1.13(VIN_B1) U1.18(VANA) U1.22(VIN_B3) U1.26(VIN_B2)
AR_1P0_RF1: C75.2 C113.1 L12.2
AR_1P0_RF2: C111.2 C121.1 L14.2
AR_1P2: C76.1 L13.2
AR_1V8: C73.2 C112.1 L11.2
GND: C30.2 C31.2 C32.2 C33.1 C34.1 C44.1 C45.1 C46.1 C47.1 C48.1 C49.1 C50.2 C51.2 C52.2 C53.2 C54.1 C73.1 C75.1 C76.2 C77.1 C111.1 C112.2 C113.2 C121.2 LD1.2(K) R37.1 R52.1 TP12.1 U1.4(AGND) U1.11(PGND_B01) U1.17(AGND) U1.24(PGND_B23) U1.27(AGND)
PMIC_1V0: C46.2 C49.2 C54.2 L4.1 L12.1 L14.1 U1.1(FB_B2)
PMIC_1V2: C45.2 C77.2 L3.1 L13.1 U1.14(FB_B1)
PMIC_1V8: C47.2 C48.2 L5.1 L11.1 U1.21(FB_B3)
PMIC_3V3: C44.2 L2.1 R31.1 TP5.1 U1.8(FB_B0)
PMICVIO_3V3: R25.2 R26.2 R33.2 R34.2 R35.2 R36.2 R50.1 R52.2
AR_SCL: R32.1 ; port AR_SCL
AR_SDA: R28.1 ; port AR_SDA
PGOOD: R31.2 R37.2 ; port PGOOD
PMIC_CLK: U1.3(CLKIN) ; port PMIC_CLK
PMIC_EN1: R34.1 U1.7(EN1) ; port PMIC_EN1
PMIC_EN2: R35.1 U1.15(EN2)
PMIC_EN3: R36.1 U1.2(EN3)
PMIC_NINT: R26.1 U1.19(~{INT})
PMIC_NRST: R33.1 U1.20(~{RST})
PMIC_PGOOD: R25.1 U1.16(PGOOD)
PMIC_SCL: R32.2 U1.5(SCL)
PMIC_SDA: R28.2 U1.6(SDA)
SW0: L2.2 R53.2 U1.10(SW_B0)
SW0_CAP: C31.1 R53.1
SW1: L3.2 R54.2 U1.12(SW_B1)
SW1_CAP: C32.1 R54.1
SW2: L4.2 R55.2 U1.25(SW_B2)
SW2_CAP: C33.2 R55.1
SW3: L5.2 R56.2 U1.23(SW_B3)
SW3_CAP: C34.2 R56.1
NetLD1_1: LD1.1(A) R39.2

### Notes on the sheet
- PMIC (3.3V, 1.2V, 1.0V, 1.8V OUTPUTS)
- 5V LED INDICATION
- LDO BYPASS

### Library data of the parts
C30 = CMP-0078265-1: as C56 on sheet PROC106A1_AOP_PWR
C31-C34 = CMP-0085511-1: CAP, CERM, 390 pF, 50 V,+/- 5%, C0G/NP0, AEC-Q200 Grade 1, 0402; Manufacturer: TDK; AEC Qualified: Y; SizeZ_mm: 0.6; VDC_V: 50V; AEC Category: Q200; AEC Grade: 1; Cap_Case: 0402; Polarized: N; SizeArea_mm2: 0.5; SizeAreaWB_mm2: 3; TaMax_C: 125°C; TaMin_C: -55°C; U/M: EA; Value: 390pF
C44-C47 = CMP-0008811-3: CAP, CERM, 22 uF, 10 V, +/- 10%, X7R, AEC-Q200 Grade 1, 1206; Manufacturer: MuRata; AEC Qualified: Y; Cap_F: 22µF; SizeZ_mm: 1.8; VDC_V: 10V; AEC Category: Q200; AEC Grade: 1; Cap_Case: 1206; Polarized: N; SizeArea_mm2: 5.12; SizeAreaWB_mm2: 10.92; SizeX_mm: 3.2; SizeY_mm: 1.6; TaMax_C: 125°C; TaMin_C: -55°C; U/M: EA; Value1: Unknown; Value: 22uF
C48 C49 C54 C73 C75 C77 C111 = CMP-0008811-3: CAP, CERM, 22 uF, 10 V, +/- 10%, X7R, AEC-Q200 Grade 1, 1206; Manufacturer: MuRata; Cap_F: 22µF; AEC Qualified: Y; SizeZ_mm: 1.8; VDC_V: 10V; AEC Category: Q200; AEC Grade: 1; Cap_Case: 1206; Polarized: N; SizeArea_mm2: 5.12; SizeAreaWB_mm2: 10.92; SizeX_mm: 3.2; SizeY_mm: 1.6; TaMax_C: 125°C; TaMin_C: -55°C; U/M: EA; Value1: Unknown; Value: 22uF
C50-C53 C76 C112 C113 C121 = CMP-0008017-2: as C55 on sheet PROC106A1_AOP_PWR
L2-L5 = CMP-0058944-1: Inductor, Shielded, 470 nH, 4.7 A, 0.021 ohm, SMD; Manufacturer: MuRata Toko; DCR_ohm: 0.021; Irms: 4.7A @ 40C rise; Isat: 6.1A @ 30% inductance drop; SizeZ_mm: 1.2; AEC Category: Q200; Imax_A: 4.7A; SizeArea_mm2: 5; SizeAreaWB_mm2: 10.5; SizeX_mm: 2.5; SizeY_mm: 2; Value: 470nH
L11-L14 = CMP-0089947-1: 100 Ohms @ 100MHz 1 Power Line Ferrite Bead 0805 (2012 Metric) 4A 20mOhm; Manufacturer: TDK; DCR_ohm: 0.02; SizeZ_mm: 1.05mm; AEC Grade: Grade 1; AEC Qualified: Yes; Impedance At Frequency: 100Ω @ 100MHz; Tolerance_%: 25%
LD1 = CMP-0067682-2: LED, Green, SMD; Manufacturer: Kingbright; Angle: 120.0; Power_TotalModule: 75mW; SizeZ_mm: 0.6; Vf_V: 2.1V; Vr_V: 5V; Io_A: 20mA; Ir_A: 10µA; SizeArea_mm2: 0.5; SizeAreaWB_mm2: 3.0; SizeX_mm: 1.0; Tjmax_C: 85°C; Value1: 0.075W
R25 R26 R33 R34 = CMP-0090497-1: 4.99 kOhms ±1% 0.05W, 1/20W Chip Resistor 0201 (0603 Metric) Automotive AEC-Q200 Thick Film; Manufacturer: Panasonic Electronic Components; AEC Grade: Grade 1; AEC Qualified: Yes; Power_W: 50mW; SizeZ_mm: 0.26mm; TempCo: 200ppm/°C; VDC_V: 25V
R28 R31 R32 = CMP-0065361-1: as R2 on sheet PROC106A1_AOP_IO
R35 R36 = CMP-0090084-1: as R3 on sheet PROC106A1_AOP_IO
R37 = CMP-0090298-1: as R4 on sheet PROC106A1_AOP_IO
R39 = CMP-0090502-1: 510 Ohms ±5% 0.05W, 1/20W Chip Resistor 0201 (0603 Metric) Automotive AEC-Q200 Thick Film; Manufacturer: Panasonic Electronic Components; AEC Grade: Grade 1; AEC Qualified: Yes; Power_W: 50mW; SizeZ_mm: 0.26mm; TempCo: 200ppm/°C; VDC_V: 25V
R50 = CMP-0090500-1: as R75 on sheet PROC106A1_AOP_IO
R52 = CMP-0090496-1: Res Thick Film 0201 1.96K Ohm 1% 1/20W 200ppm/C Molded SMD T/R; Manufacturer: Panasonic; AEC Grade: Grade 1; AEC Qualified: Yes; Power_W: 50mW; SizeZ_mm: 0.26mm; TempCo: 200ppm/°C; VDC_V: 25V
R53-R56 = CMP-0026363-2: RES, 3.83, 1%, 0.063 W, AEC-Q200 Grade 0, 0402; Manufacturer: Vishay-Dale; TempCo: 100 ppm/C; AEC Qualified: Y; Power_W: 63mW; VDC_V: 50V; SizeZ_mm: 0.6; AEC Category: Q200; AEC Grade: 0; EIA_Code: E96; SizeArea_mm2: 0.5; SizeX_mm: 1; Value2: 0.063W; Value: 3.83; Value_Code: 3R83
TP5 TP12 = CMP-0078143-3: TEST POINT.  No entry in BOM.
U1 = CMP-0079120-2: 4-A + 2.5-A + Two 1.5-A Buck Converters With Integrated Switches, RNF0026C (VQFN-HR-26); Alternate PartNumber: LP87524JRNFTQ1; Alternate Manufacturer: Texas Instruments; SizeAreaWB_mm2: 27.5; SizeZ_mm: 0.9; SizeX_mm: 4; SizeY_mm: 4.5; SizeArea_mm2: 18; CompType: IC; AEC Qualified: Y; AEC Category: Q200

## Sheet PROC106A1_FLASH_USB_TO_UART.SchDoc: FLASH&USB_TO_UART
size 431 x 279 mm; Date: Not shown in title block; ApprovedBy: Not shown in title block; CheckedBy: Not shown in title block; Author: Not shown in title block; CompanyName: Not shown in title block; DrawnBy: Antony/Anand Ram; Engineer: Not shown in title block; Organization: Not shown in title block; Address1: Not shown in title block; Address2: Not shown in title block; Address3: Not shown in title block; Address4: Not shown in title block; DocumentNumber: 6; Revision: Use project parameter SCH_Rev; SheetNumber: 6; SheetTotal: 12; PageSetup: Record=PageOptions¦CenterHorizontal=True¦CenterVertical=True¦PrintScale=1.00¦XCorrection=1.00¦YCorrection=1.00¦PrintKind=0¦BorderSize=5000000¦LeftOffset=0¦BottomOffset=0¦Orientation=2¦PaperLength=1000¦PaperWidth=1000¦Scale=100¦PaperSource=15¦PrintQuality=600¦MediaType=1¦DitherType=10¦PaperKind=Letter¦PrintScaleMode=1
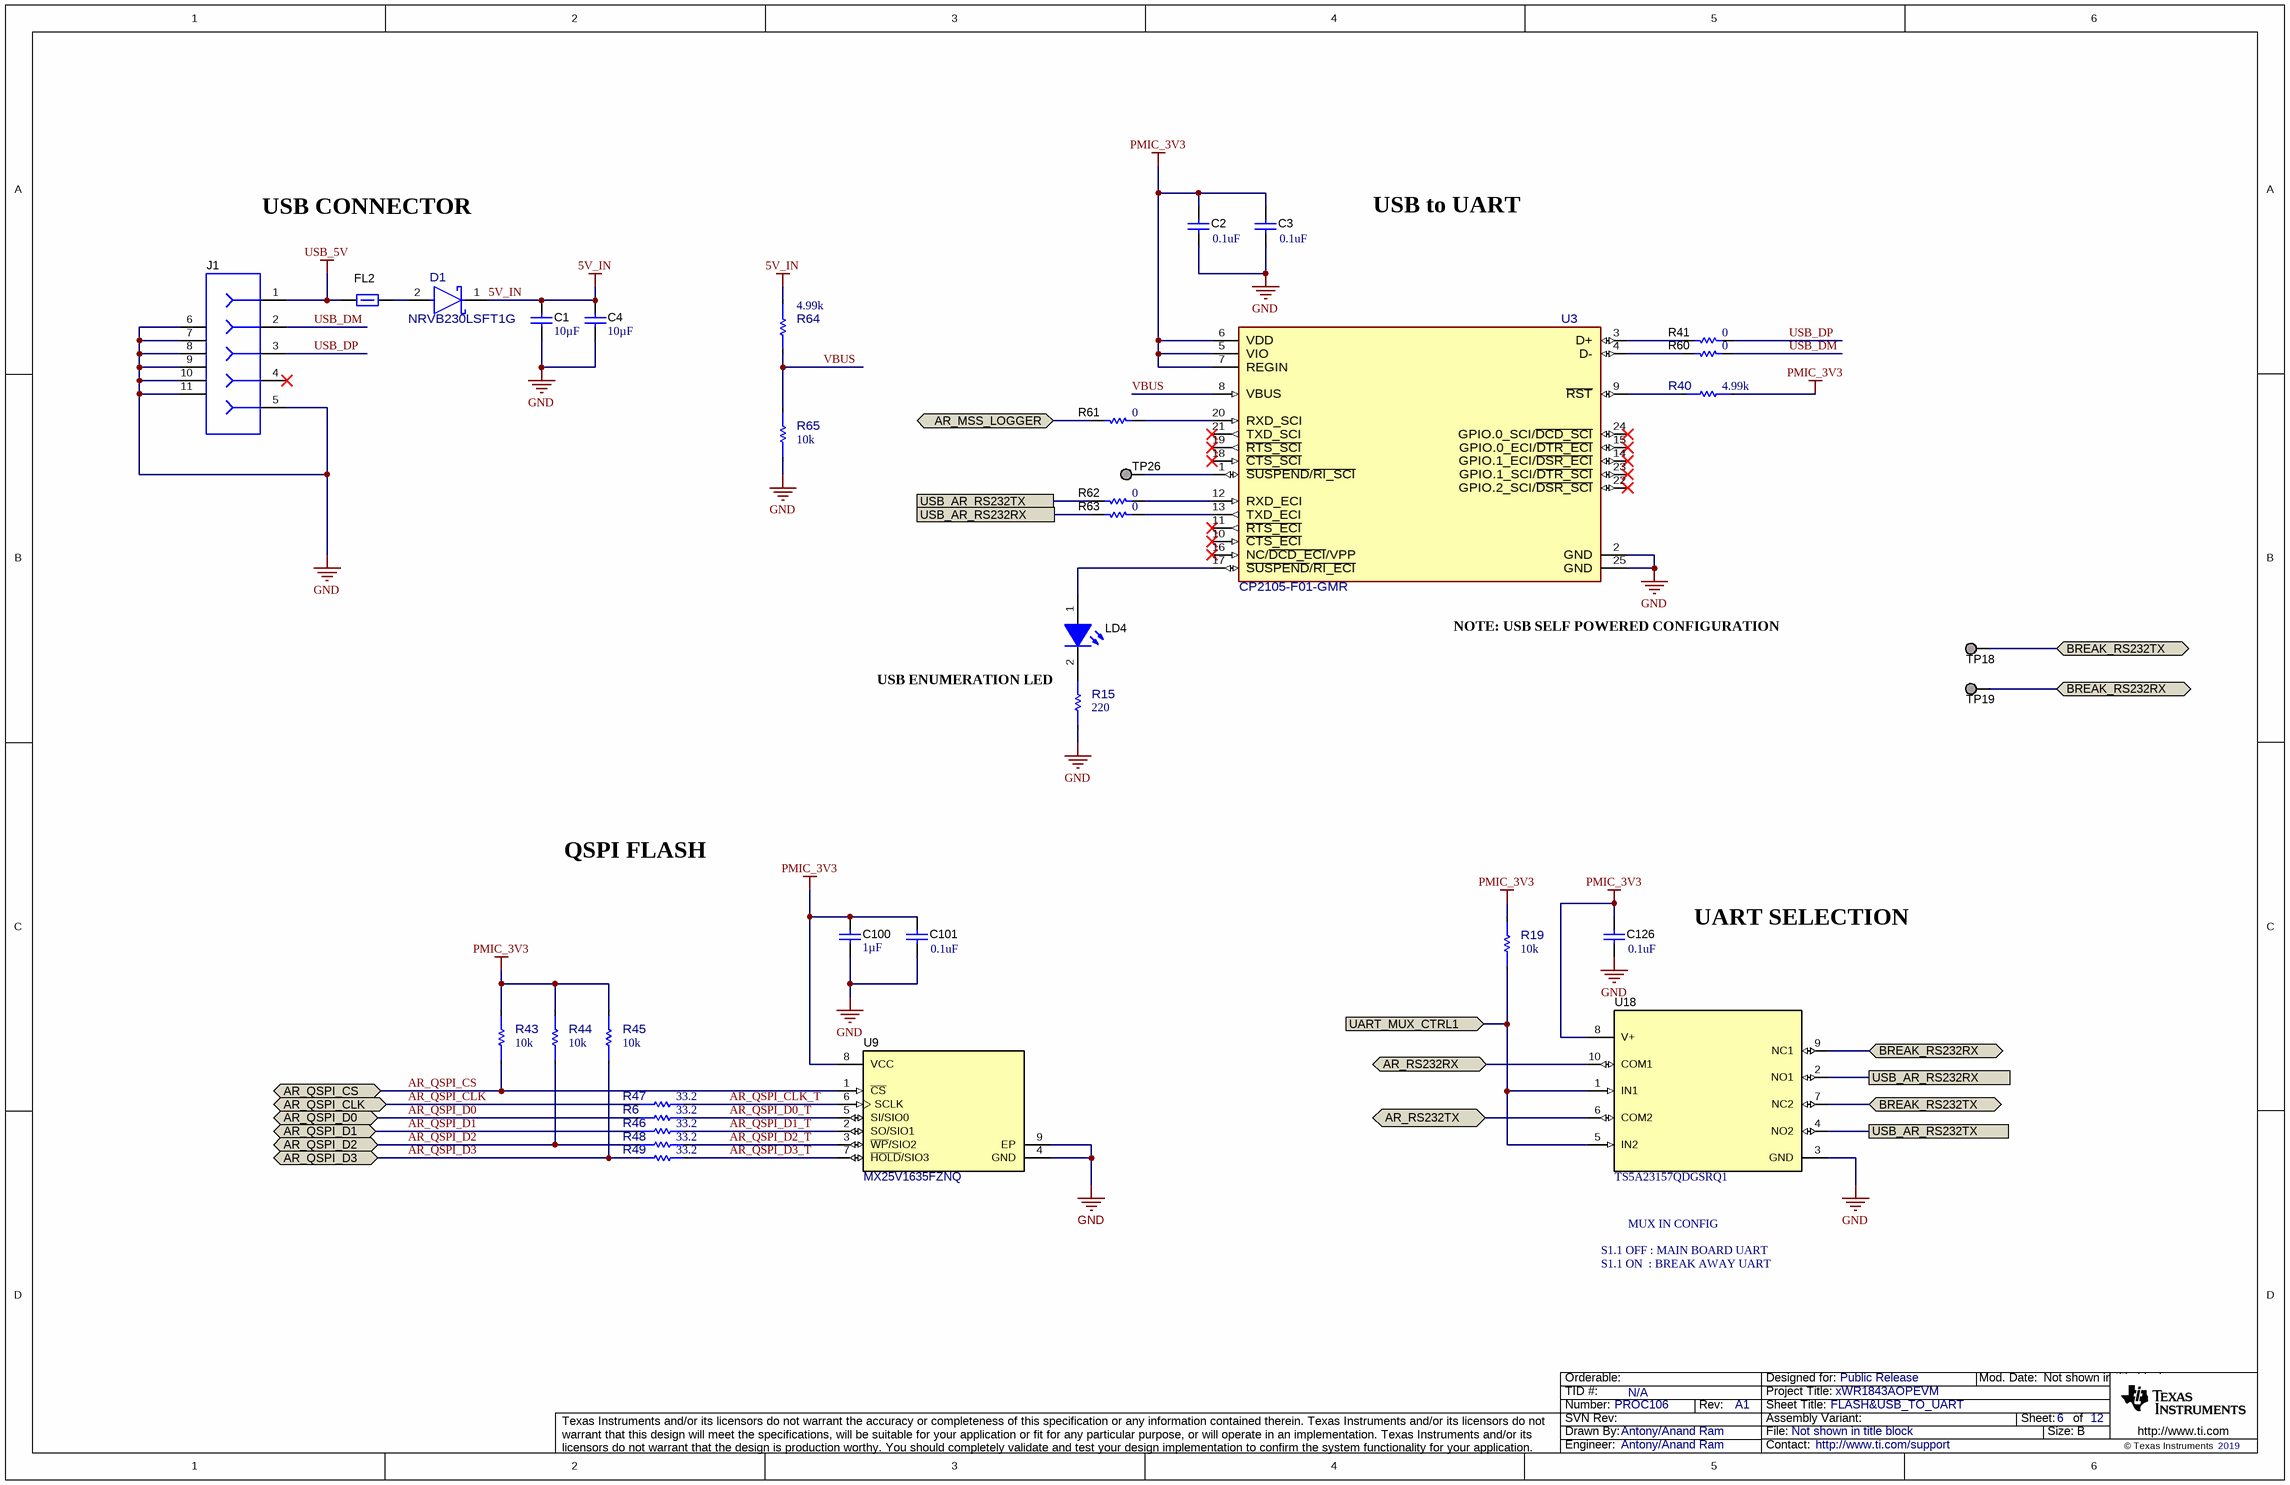
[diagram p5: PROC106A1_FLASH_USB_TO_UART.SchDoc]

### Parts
C1  Cap_F: 10µF  [0805L]  (hidden comment: GCM21BR71A106KE22L)
C2  ValueDisplayed: 0.1uF  [0402L]  (hidden comment: GCM155R71C104KA55D)
C3  ValueDisplayed: 0.1uF  [0402L]  (hidden comment: GCM155R71C104KA55D)
C4  Cap_F: 10µF  [0805L]  (hidden comment: GCM21BR71A106KE22L)
C100  Cap_F: 1µF  [0603L]  (hidden comment: GCM188R71C105KA64D)
C101  ValueDisplayed: 0.1uF  [0402L]  (hidden comment: GCM155R71C104KA55D)
C126  ValueDisplayed: 0.1uF  [0402L]  (hidden comment: GCM155R71C104KA55D)
D1  NRVB230LSFT1G  [FP-NRVB230LSFT1G_SOD-123F-MFG]
FL2  BLM15PD300SZ1D  [0402L]  (value not drawn)
J1  105017-0001  [CONN_105017-0001]  (value not drawn)
LD4  APHHS1005CGCK  [APHHS1005_Green]  (value not drawn)
R6  value 33.2  [FP-ERJ-1GNF33R2C_0201-IPC_C]  (hidden comment: ERJ-1GNF33R2C)
R15  value 220  [FP-ERJ-1GNJ221C_0201-IPC_C]  (hidden comment: ERJ-1GNJ221C)
R19  value 10k  [FP-ERA-1AEB103C_0201-IPC_C]  (hidden comment: ERA-1AEB103C)
R40  value 4.99k  [FP-ERJ-1GNF4991C_0201-IPC_C]  (hidden comment: ERJ-1GNF4991C)
R41  ValueDisplayed: 0  [0201L]  (hidden comment: ERJ-1GN0R00C)
R43  value 10k  [FP-ERA-1AEB103C_0201-IPC_C]  (hidden comment: ERA-1AEB103C)
R44  value 10k  [FP-ERA-1AEB103C_0201-IPC_C]  (hidden comment: ERA-1AEB103C)
R45  value 10k  [FP-ERA-1AEB103C_0201-IPC_C]  (hidden comment: ERA-1AEB103C)
R46  value 33.2  [FP-ERJ-1GNF33R2C_0201-IPC_C]  (hidden comment: ERJ-1GNF33R2C)
R47  value 33.2  [FP-ERJ-1GNF33R2C_0201-IPC_C]  (hidden comment: ERJ-1GNF33R2C)
R48  value 33.2  [FP-ERJ-1GNF33R2C_0201-IPC_C]  (hidden comment: ERJ-1GNF33R2C)
R49  value 33.2  [FP-ERJ-1GNF33R2C_0201-IPC_C]  (hidden comment: ERJ-1GNF33R2C)
R60  ValueDisplayed: 0  [0201L]  (hidden comment: ERJ-1GN0R00C)
R61  ValueDisplayed: 0  [0201L]  (hidden comment: ERJ-1GN0R00C)
R62  ValueDisplayed: 0  [0201L]  (hidden comment: ERJ-1GN0R00C)
R63  ValueDisplayed: 0  [0201L]  (hidden comment: ERJ-1GN0R00C)
R64  value 4.99k  [FP-ERJ-1GNF4991C_0201-IPC_C]  (hidden comment: ERJ-1GNF4991C)
R65  value 10k  [FP-ERA-1AEB103C_0201-IPC_C]  (hidden comment: ERA-1AEB103C)
TP18  TESTPOINT  [TP_25MIL-SMT]  (value not drawn)  (no BOM)
TP19  TESTPOINT  [TP_25MIL-SMT]  (value not drawn)  (no BOM)
TP26  TESTPOINT  [TP_25MIL-SMT]  (value not drawn)  (no BOM)
U3  CP2105-F01-GMR  [FP-CP2105-F01-GMR_QFN24-EP-IPC_A]
U9  MX25V1635FZNQ  [WSON-8L_6x5MM_EP]
U18  TS5A23157QDGSRQ1  [DGS0010A_L]

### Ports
AR_MSS_LOGGER (bidir), AR_QSPI_CLK (bidir), AR_QSPI_CS (bidir), AR_QSPI_D0 (bidir), AR_QSPI_D1 (bidir), AR_QSPI_D2 (bidir), AR_QSPI_D3 (bidir), AR_RS232RX (bidir), AR_RS232TX (bidir), BREAK_RS232RX (bidir), BREAK_RS232TX (bidir), UART_MUX_CTRL1 (in), USB_AR_RS232RX, USB_AR_RS232TX

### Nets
5V_IN: C1.2 C4.1 D1.1(CATHODE) R64.1
GND: C1.1 C2.2 C3.2 C4.2 C100.1 C101.1 C126.1 J1.5 J1.6 J1.7 J1.8 J1.9 J1.10 J1.11 R15.1 R65.1 U3.2(GND) U3.25(GND) U9.4(GND) U9.9(EP) U18.3(GND)
PMIC_3V3: C2.1 C3.1 C100.2 C101.2 C126.2 R19.2 R40.1 R43.2 R44.2 R45.2 U3.5(VIO) U3.6(VDD) U3.7(REGIN) U9.8(VCC) U18.8(V+)
USB_5V: FL2.1 J1.1
AR_MSS_LOGGER: R61.1 ; port AR_MSS_LOGGER
AR_QSPI_CLK: R47.1 ; port AR_QSPI_CLK
AR_QSPI_CLK_T: R47.2 U9.6(SCLK)
AR_QSPI_CS: R43.1 U9.1(~{CS}) ; port AR_QSPI_CS
AR_QSPI_D0: R6.1 ; port AR_QSPI_D0
AR_QSPI_D0_T: R6.2 U9.5(SI/SIO0)
AR_QSPI_D1: R46.1 ; port AR_QSPI_D1
AR_QSPI_D1_T: R46.2 U9.2(SO/SIO1)
AR_QSPI_D2: R44.1 R48.1 ; port AR_QSPI_D2
AR_QSPI_D2_T: R48.2 U9.3(~{WP}/SIO2)
AR_QSPI_D3: R45.1 R49.1 ; port AR_QSPI_D3
AR_QSPI_D3_T: R49.2 U9.7(~{HOLD}/SIO3)
AR_RS232RX: U18.10(COM1) ; port AR_RS232RX
AR_RS232TX: U18.6(COM2) ; port AR_RS232TX
BREAK_RS232RX: TP19.1 U18.9(NC1) ; port BREAK_RS232RX
BREAK_RS232TX: TP18.1 U18.7(NC2) ; port BREAK_RS232TX
UART_MUX_CTRL1: R19.1 U18.1(IN1) U18.5(IN2) ; port UART_MUX_CTRL1
USB_AR_RS232RX: R63.1 U18.2(NO1) ; port USB_AR_RS232RX
USB_AR_RS232TX: R62.1 U18.4(NO2) ; port USB_AR_RS232TX
USB_DM: J1.2 R60.2
USB_DP: J1.3 R41.2
VBUS: R64.2 R65.2 U3.8(VBUS)
NetD1_2: D1.2(ANODE) FL2.2
NetLD4_1: LD4.1(A) U3.17(~{SUSPEND}/~{RI_ECI})
NetLD4_2: LD4.2(K) R15.2
NetR40_2: R40.2 U3.9(~{RST})
NetR41_1: R41.1 U3.3(D+)
NetR60_1: R60.1 U3.4(D-)
NetR61_2: R61.2 U3.20(RXD_SCI)
NetR62_2: R62.2 U3.12(RXD_ECI)
NetR63_2: R63.2 U3.13(TXD_ECI)
NetTP26_1: TP26.1 U3.1(~{SUSPEND}/~{RI_SCI})

Not connected (* = marked no-connect by the designer): J1 4*; U3 10(~{CTS_ECI})* 11(~{RTS_ECI})* 14(GPIO.1_ECI/~{DSR_ECI})* 15(GPIO.0_ECI/~{DTR_ECI})* 16(NC/~{DCD_ECI}/VPP)* 18(~{CTS_SCI})* 19(~{RTS_SCI})* 21(TXD_SCI)* 22(GPIO.2_SCI/~{DSR_SCI})* 23(GPIO.1_SCI/~{DTR_SCI})* 24(GPIO.0_SCI/~{DCD_SCI})*

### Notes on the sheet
- USB CONNECTOR
- USB to UART
- (near U3) NOTE: USB SELF POWERED CONFIGURATION
- USB ENUMERATION LED
- QSPI FLASH
- UART SELECTION
- MUX IN CONFIG
- S1.1 ON  : BREAK AWAY UART
- S1.1 OFF : MAIN BOARD UART

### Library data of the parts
C1 C4 = CMP-0008017-2: as C55 on sheet PROC106A1_AOP_PWR
C2 C3 C101 C126 = CMP-0006351-2: as C130 on sheet PROC106A1_AOP_IO
C100 = CMP-0007136-5: CAP, CERM, 1 uF, 16 V, +/- 10%, X7R, AEC-Q200 Grade 1, 0603; Manufacturer: MuRata; AEC Qualified: Y; SizeZ_mm: 1; VDC_V: 16V; AEC Category: Q200; Cap_Case: 0603; Polarized: N; SizeArea_mm2: 1.28; SizeAreaWB_mm2: 4.68; SizeX_mm: 1.6; SizeY_mm: 0.8; TaMax_C: 125°C; TaMin_C: -55°C; U/M: EA; Value1: Unknown; Value: 1uF
D1 = CMP-0090508-1: Diode Schottky 30V 2A Surface Mount SOD-123FL; Manufacturer: ON Semiconductor; TJmax_C: 125°C; SizeZ_mm: 0.98mm; AEC Qualified: Yes; AEC Grade: Grade 1; Max Surge Forward Current: 40A; Peak Reverse Current: 1mA; Standoff Height: 0mm
FL2 = CMP-0078934-1: Inductor, Ferrite Bead, Ferrite, 2.2 A, 0.035 ohm, AEC-Q200 Grade 1, SMD; Manufacturer: MuRata; AEC Category: Q200; AEC Grade: 1; AEC Qualified: Y; DCR_ohm: 0.035; Imax_A: 2.2A; SizeArea_mm2: 0.5; SizeAreaWB_mm2: 3; SizeZ_mm: 0.6
J1 = CMP-0055293-1: Connector, Receptacle, Micro-USB Type B, R/A, Bottom Mount SMT; Manufacturer: Molex; CNHeader: FALSE; CompType: USB; CT: TRUE; Gender: Female; Green_Lifecycle: Active; Green_REACh: Passed
LD4 = CMP-0067682-2: as LD1 on sheet PROC106A1_PMIC
R6 R46-R49 = CMP-0089575-2: Res Thick Film 0201 33.2 Ohm 1% 0.05W(1/20W) ±200ppm/C Pad SMD Automotive T/R; Manufacturer: Panasonic; AEC Grade: Grade 1; AEC Qualified: Yes; Power_W: 50mW; SizeZ_mm: 0.26mm; TempCo: 200ppm/°C; VDC_V: 25V
R15 = CMP-0090501-1: 220 Ohms ±5% 0.05W, 1/20W Chip Resistor 0201 (0603 Metric) Automotive AEC-Q200 Thick Film; Manufacturer: Panasonic Electronic Components; AEC Grade: Grade 1; AEC Qualified: Yes; Power_W: 50mW; SizeZ_mm: 0.26mm; TempCo: 200ppm/°C; VDC_V: 25V
R19 R43-R45 R65 = CMP-0090084-1: as R3 on sheet PROC106A1_AOP_IO
R40 R64 = CMP-0090497-1: as R25 on sheet PROC106A1_PMIC
R41 R60-R63 = CMP-0065361-1: as R2 on sheet PROC106A1_AOP_IO
TP18 TP19 TP26 = CMP-0078143-3: TEST POINT.  No entry in BOM.
U3 = CMP-0087172-1: I/O Controller Interface IC USB to Dual UART bridge; Manufacturer: Silicon Labs; SizeZ_mm: 0.8mm
U9 = CMP-0079267-1: 2.3V-3.6V, 16M-BIT [x 1/x 2/x 4] CMOS FLASH Memory, WSON-8; Manufacturer: Macronix International Co., LTD; SizeArea_mm2: 30; SizeAreaWB_mm2: 56; SizeX_mm: 6; SizeY_mm: 5; SizeZ_mm: 0.8
U18 = CMP-0074341-1: Automotive Catalog Dual 15-Ohm SPDT Analog Switch, DGS0010A (VSSOP-10); Alternate Manufacturer: Texas Instruments; CompType: IC; SizeArea_mm2: 14.7; SizeAreaWB_mm2: 23.6; SizeX_mm: 4.9; SizeY_mm: 3.0; SizeZ_mm: 1.1; U/M: EA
